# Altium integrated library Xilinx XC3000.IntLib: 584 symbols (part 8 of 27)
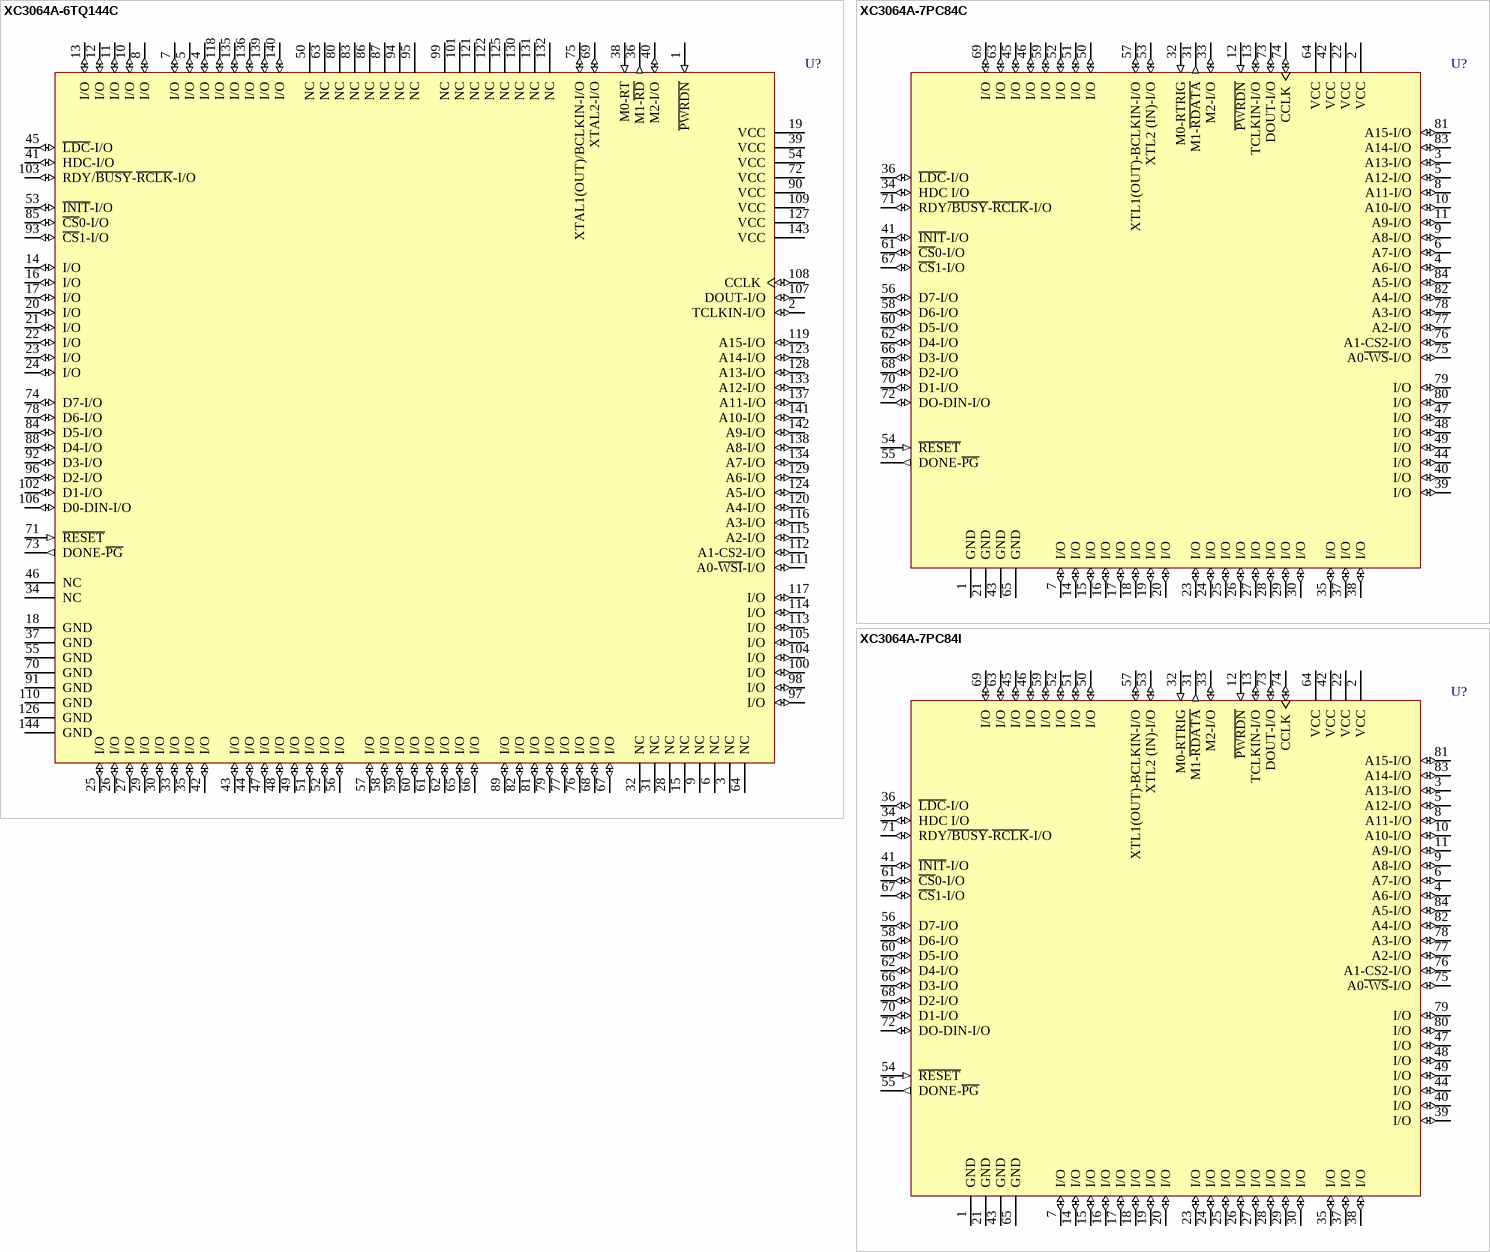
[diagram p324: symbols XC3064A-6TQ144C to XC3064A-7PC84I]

## XC3064A-7PC84I
designator U?
Logic Cell Array with 224 CLBs, with 70 I/O Pins, 84-Pin PLCC, Industrial Grade; ComponentAvailability: Not for New Design
footprint PC84_N (Leaded Chip Carrier, 84-Leads, Body 29.3x29.3mm, Pitch 1.27mm, IPC Medium Density)
footprint PC84_L (Leaded Chip Carrier, 84-Leads, Body 29.3x29.3mm, Pitch 1.27mm, IPC High Density)
footprint PC84_M (Leaded Chip Carrier, 84-Leads, Body 29.3x29.3mm, Pitch 1.27mm, IPC Low Density)
3D model XC3064A-PC84 (84-Pin Plastic Leaded Chip Carrier (PC84))
pins: 1 GND (power), 2 VCC (power), 3 A13-I/O (io), 4 A6-I/O (io), 5 A12-I/O (io), 6 A7-I/O (io), 7 I/O (io), 8 A11-I/O (io), 9 A8-I/O (io), 10 A10-I/O (io), 11 A9-I/O (io), 12 ~{PWRDN} (in), 13 TCLKIN-I/O (io), 14 I/O (io), 15 I/O (io), 16 I/O (io), 17 I/O (io), 18 I/O (io), 19 I/O (io), 20 I/O (io), 21 GND (power), 22 VCC (power), 23 I/O (io), 24 I/O (io), 25 I/O (io), 26 I/O (io), 27 I/O (io), 28 I/O (io), 29 I/O (io), 30 I/O (io), 31 M1-~{RDATA} (out), 32 M0-RTRIG (in), 33 M2-I/O (io), 34 HDC I/O (io), 35 I/O (io), 36 ~{LDC}-I/O (io), 37 I/O (io), 38 I/O (io), 39 I/O (io), 40 I/O (io), 41 ~{INIT}-I/O (io), 42 VCC (power), 43 GND (power), 44 I/O (io), 45 I/O (io), 46 I/O (io), 47 I/O (io), 48 I/O (io), 49 I/O (io), 50 I/O (io), 51 I/O (io), 52 I/O (io), 53 XTL2 (IN)-I/O (io), 54 ~{RESET} (in), 55 DONE-~{PG} (out), 56 D7-I/O (io), 57 XTL1(OUT)-BCLKIN-I/O (io), 58 D6-I/O (io), 59 I/O (io), 60 D5-I/O (io), 61 ~{CS}0-I/O (io), 62 D4-I/O (io), 63 I/O (io), 64 VCC (power), 65 GND (power), 66 D3-I/O (io), 67 ~{CS}1-I/O (io), 68 D2-I/O (io), 69 I/O (io), 70 D1-I/O (io), 71 RDY~{/BUSY}-~{RCLK}-I/O (io), 72 DO-DIN-I/O (io), 73 DOUT-I/O (io), 74 CCLK (io), 75 A0~{-WS}-I/O (io), 76 A1-CS2-I/O (io), 77 A2-I/O (io), 78 A3-I/O (io), 79 I/O (io), 80 I/O (io), 81 A15-I/O (io), 82 A4-I/O (io), 83 A14-I/O (io), 84 A5-I/O (io)

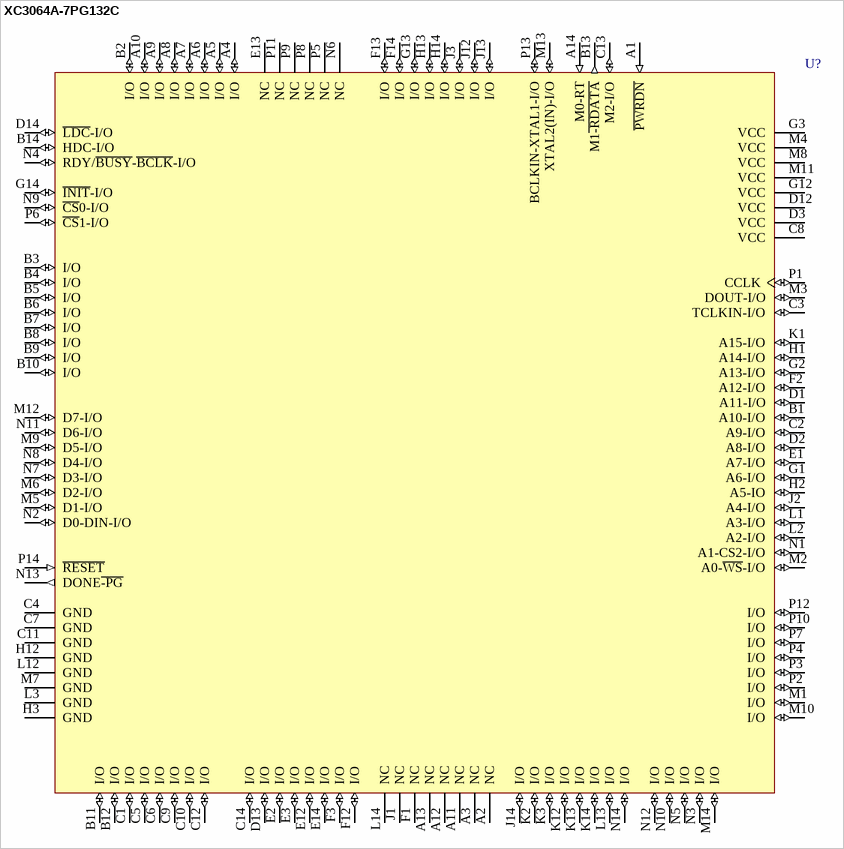
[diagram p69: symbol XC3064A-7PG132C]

## XC3064A-7PG132C
designator U?
Logic Cell Array with 224 CLBs, with 96 I/O Pins, 132-Pin PGA, Commercial Grade; ComponentAvailability: Not for New Design
footprint PG132 (PGA, 132-Leads, Body 37x37mm, Pitch 2.54mm)
3D model XC3064A-PG132 (132-Pin Ceramic Pin Grid Array (PG132))
pins: A1 ~{PWRDN} (in), A2 NC, A3 NC, A4 I/O (io), A5 I/O (io), A6 I/O (io), A7 I/O (io), A8 I/O (io), A9 I/O (io), A10 I/O (io), A11 NC, A12 NC, A13 NC, A14 M0-RT (in), B1 A10-I/O (io), B2 I/O (io), B3 I/O (io), B4 I/O (io), B5 I/O (io), B6 I/O (io), B7 I/O (io), B8 I/O (io), B9 I/O (io), B10 I/O (io), B11 I/O (io), B12 I/O (io), B13 M1~{-RDATA} (out), B14 HDC-I/O (io), C1 I/O (io), C2 A9-I/O (io), C3 TCLKIN-I/O (io), C4 GND (power), C5 I/O (io), C6 I/O (io), C7 GND (power), C8 VCC (power), C9 I/O (io), C10 I/O (io), C11 GND (power), C12 I/O (io), C13 M2-I/O (io), C14 I/O (io), D1 A11-I/O (io), D2 A8-I/O (io), D3 VCC (power), D12 VCC (power), D13 I/O (io), D14 ~{LDC}-I/O (io), E1 A7-I/O (io), E2 I/O (io), E3 I/O (io), E12 I/O (io), E13 NC, E14 I/O (io), F1 NC, F2 A12-I/O (io), F3 I/O (io), F12 I/O (io), F13 I/O (io), F14 I/O (io), G1 A6-I/O (io), G2 A13-I/O (io), G3 VCC (power), G12 VCC (power), G13 I/O (io), G14 ~{INIT}-I/O (io), H1 A14-I/O (io), H2 A5-IO (io), H3 GND (power), H12 GND (power), H13 I/O (io), H14 I/O (io), J1 NC, J2 A4-I/O (io), J3 I/O (io), J12 I/O (io), J13 I/O (io), J14 I/O (io), K1 A15-I/O (io), K2 I/O (io), K3 I/O (io), K12 I/O (io), K13 I/O (io), K14 I/O (io), L1 A3-I/O (io), L2 A2-I/O (io), L3 GND (power), L12 GND (power), L13 I/O (io), L14 NC, M1 I/O (io), M2 A0-~{WS}-I/O (io), M3 DOUT-I/O (io), M4 VCC (power), M5 D1-I/O (io), M6 D2-I/O (io), M7 GND (power), M8 VCC (power), M9 D5-I/O (io), M10 I/O (io), M11 VCC (power), M12 D7-I/O (io), M13 XTAL2(IN)-I/O (io), M14 I/O (io), N1 A1-CS2-I/O (io), N2 D0-DIN-I/O (io), N3 I/O (io), N4 RDY/~{BUSY}-~{BCLK}-I/O (io), N5 I/O (io), N6 NC, N7 D3-I/O (io), N8 D4-I/O (io), N9 ~{CS}0-I/O (io), N10 I/O (io), N11 D6-I/O (io), N12 I/O (io), N13 DONE~{-PG} (out), N14 I/O (io), P1 CCLK (io), P2 I/O (io), P3 I/O (io), P4 I/O (io), P5 NC, P6 ~{CS}1-I/O (io), P7 I/O (io), P8 NC, P9 NC, P10 I/O (io), P11 NC, P12 I/O (io), P13 BCLKIN-XTAL1-I/O (io), P14 ~{RESET} (in)

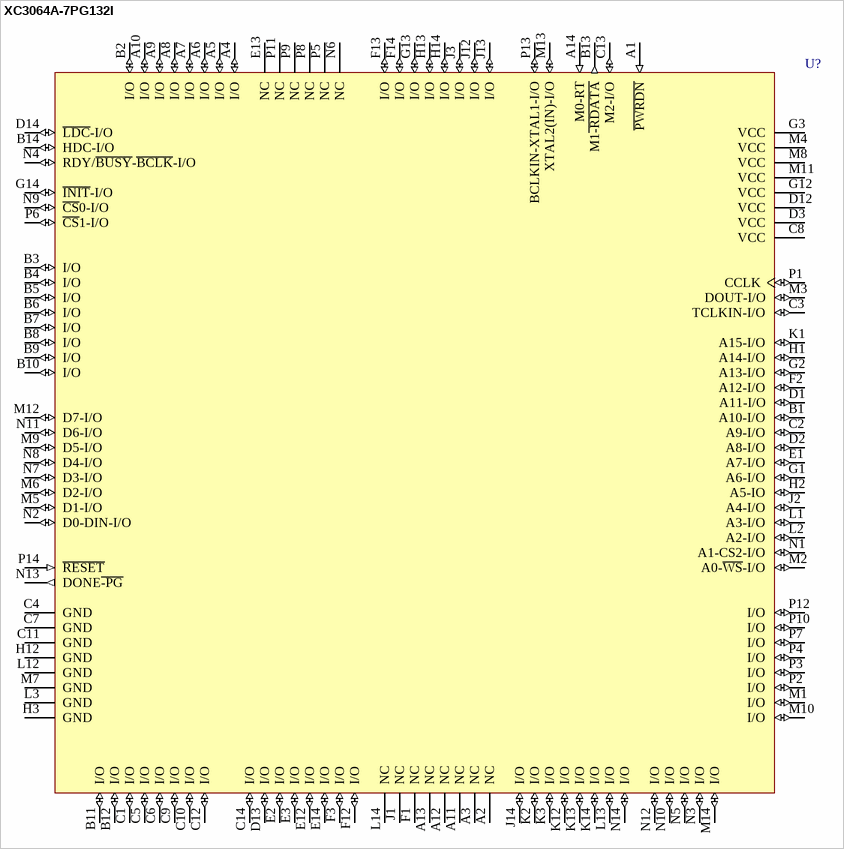
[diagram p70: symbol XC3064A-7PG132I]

## XC3064A-7PG132I
designator U?
Logic Cell Array with 224 CLBs, with 96 I/O Pins, 132-Pin PGA, Industrial Grade; ComponentAvailability: Not for New Design
footprint PG132 (PGA, 132-Leads, Body 37x37mm, Pitch 2.54mm)
3D model XC3064A-PG132 (132-Pin Ceramic Pin Grid Array (PG132))
pins: A1 ~{PWRDN} (in), A2 NC, A3 NC, A4 I/O (io), A5 I/O (io), A6 I/O (io), A7 I/O (io), A8 I/O (io), A9 I/O (io), A10 I/O (io), A11 NC, A12 NC, A13 NC, A14 M0-RT (in), B1 A10-I/O (io), B2 I/O (io), B3 I/O (io), B4 I/O (io), B5 I/O (io), B6 I/O (io), B7 I/O (io), B8 I/O (io), B9 I/O (io), B10 I/O (io), B11 I/O (io), B12 I/O (io), B13 M1~{-RDATA} (out), B14 HDC-I/O (io), C1 I/O (io), C2 A9-I/O (io), C3 TCLKIN-I/O (io), C4 GND (power), C5 I/O (io), C6 I/O (io), C7 GND (power), C8 VCC (power), C9 I/O (io), C10 I/O (io), C11 GND (power), C12 I/O (io), C13 M2-I/O (io), C14 I/O (io), D1 A11-I/O (io), D2 A8-I/O (io), D3 VCC (power), D12 VCC (power), D13 I/O (io), D14 ~{LDC}-I/O (io), E1 A7-I/O (io), E2 I/O (io), E3 I/O (io), E12 I/O (io), E13 NC, E14 I/O (io), F1 NC, F2 A12-I/O (io), F3 I/O (io), F12 I/O (io), F13 I/O (io), F14 I/O (io), G1 A6-I/O (io), G2 A13-I/O (io), G3 VCC (power), G12 VCC (power), G13 I/O (io), G14 ~{INIT}-I/O (io), H1 A14-I/O (io), H2 A5-IO (io), H3 GND (power), H12 GND (power), H13 I/O (io), H14 I/O (io), J1 NC, J2 A4-I/O (io), J3 I/O (io), J12 I/O (io), J13 I/O (io), J14 I/O (io), K1 A15-I/O (io), K2 I/O (io), K3 I/O (io), K12 I/O (io), K13 I/O (io), K14 I/O (io), L1 A3-I/O (io), L2 A2-I/O (io), L3 GND (power), L12 GND (power), L13 I/O (io), L14 NC, M1 I/O (io), M2 A0-~{WS}-I/O (io), M3 DOUT-I/O (io), M4 VCC (power), M5 D1-I/O (io), M6 D2-I/O (io), M7 GND (power), M8 VCC (power), M9 D5-I/O (io), M10 I/O (io), M11 VCC (power), M12 D7-I/O (io), M13 XTAL2(IN)-I/O (io), M14 I/O (io), N1 A1-CS2-I/O (io), N2 D0-DIN-I/O (io), N3 I/O (io), N4 RDY/~{BUSY}-~{BCLK}-I/O (io), N5 I/O (io), N6 NC, N7 D3-I/O (io), N8 D4-I/O (io), N9 ~{CS}0-I/O (io), N10 I/O (io), N11 D6-I/O (io), N12 I/O (io), N13 DONE~{-PG} (out), N14 I/O (io), P1 CCLK (io), P2 I/O (io), P3 I/O (io), P4 I/O (io), P5 NC, P6 ~{CS}1-I/O (io), P7 I/O (io), P8 NC, P9 NC, P10 I/O (io), P11 NC, P12 I/O (io), P13 BCLKIN-XTAL1-I/O (io), P14 ~{RESET} (in)

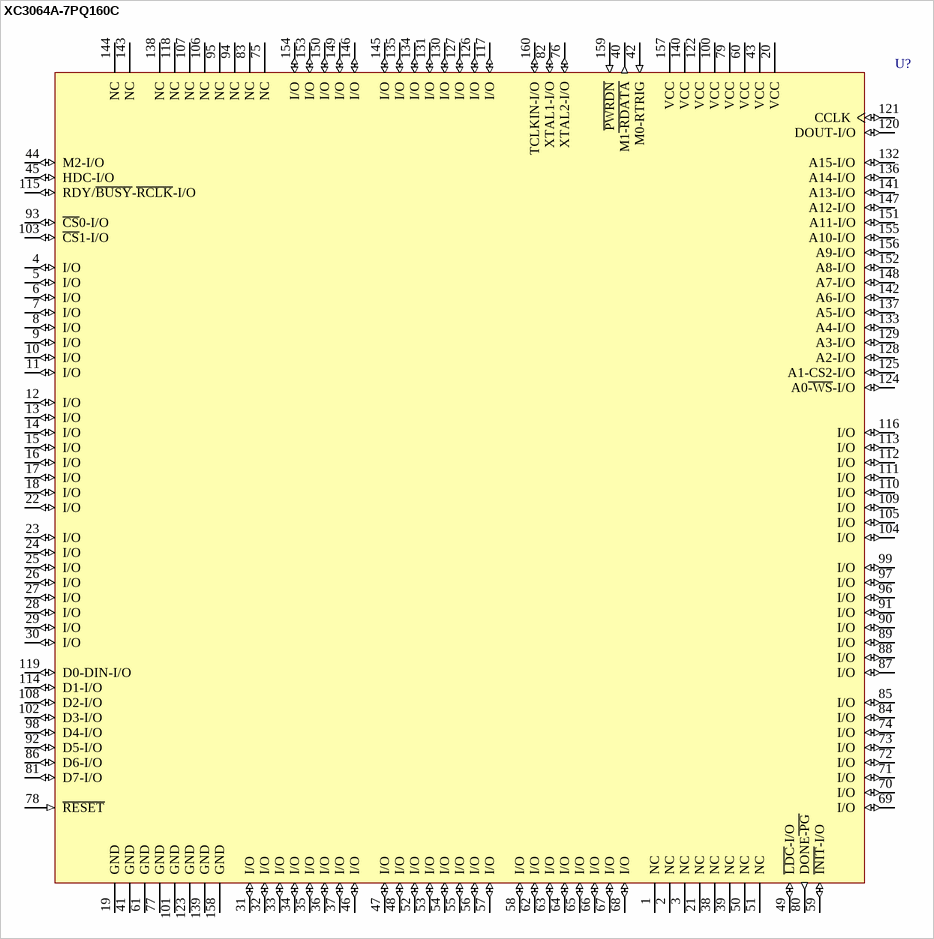
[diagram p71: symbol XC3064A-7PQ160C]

## XC3064A-7PQ160C
designator U?
Logic Cell Array with 224 CLBs, with 120 I/O Pins, 160-Pin PQFP, Commercial Grade; ComponentAvailability: Not for New Design
footprint PQ160_N (QFP, 160-Leads, Body 28 x 28mm, Pitch 0.65mm, IPC Medium Density)
footprint PQ160_L (QFP, 160-Leads, Body 28 x 28mm, Pitch 0.65mm, IPC High Density)
footprint PQ160_M (QFP, 160-Leads, Body 28 x 28mm, Pitch 0.65mm, IPC Low Density)
3D model XC3064A-PQ160 (160-Pin Plastic Quad Flat Pack (PQ160))
pins: 1 NC, 2 NC, 3 NC, 4 I/O (io), 5 I/O (io), 6 I/O (io), 7 I/O (io), 8 I/O (io), 9 I/O (io), 10 I/O (io), 11 I/O (io), 12 I/O (io), 13 I/O (io), 14 I/O (io), 15 I/O (io), 16 I/O (io), 17 I/O (io), 18 I/O (io), 19 GND (power), 20 VCC (power), 21 NC, 22 I/O (io), 23 I/O (io), 24 I/O (io), 25 I/O (io), 26 I/O (io), 27 I/O (io), 28 I/O (io), 29 I/O (io), 30 I/O (io), 31 I/O (io), 32 I/O (io), 33 I/O (io), 34 I/O (io), 35 I/O (io), 36 I/O (io), 37 I/O (io), 38 NC, 39 NC, 40 M1~{-RDATA} (out), 41 GND (power), 42 M0-RTRIG (in), 43 VCC (power), 44 M2-I/O (io), 45 HDC-I/O (io), 46 I/O (io), 47 I/O (io), 48 I/O (io), 49 ~{LDC}-I/O (io), 50 NC, 51 NC, 52 I/O (io), 53 I/O (io), 54 I/O (io), 55 I/O (io), 56 I/O (io), 57 I/O (io), 58 I/O (io), 59 ~{INIT}-I/O (io), 60 VCC (power), 61 GND (power), 62 I/O (io), 63 I/O (io), 64 I/O (io), 65 I/O (io), 66 I/O (io), 67 I/O (io), 68 I/O (io), 69 I/O (io), 70 I/O (io), 71 I/O (io), 72 I/O (io), 73 I/O (io), 74 I/O (io), 75 NC, 76 XTAL2-I/O (io), 77 GND (power), 78 ~{RESET} (in), 79 VCC (power), 80 DONE~{-PG} (out), 81 D7-I/O (io), 82 XTAL1-I/O (io), 83 NC, 84 I/O (io), 85 I/O (io), 86 D6-I/O (io), 87 I/O (io), 88 I/O (io), 89 I/O (io), 90 I/O (io), 91 I/O (io), 92 D5-I/O (io), 93 ~{CS}0-I/O (io), 94 NC, 95 NC, 96 I/O (io), 97 I/O (io), 98 D4-I/O (io), 99 I/O (io), 100 VCC (power), 101 GND (power), 102 D3-I/O (io), 103 ~{CS}1-I/O (io), 104 I/O (io), 105 I/O (io), 106 NC, 107 NC, 108 D2-I/O (io), 109 I/O (io), 110 I/O (io), 111 I/O (io), 112 I/O (io), 113 I/O (io), 114 D1-I/O (io), 115 RDY/~{BUSY}-~{RCLK}-I/O (io), 116 I/O (io), 117 I/O (io), 118 NC, 119 D0-DIN-I/O (io), 120 DOUT-I/O (io), 121 CCLK (io), 122 VCC (power), 123 GND (power), 124 A0~{-WS}-I/O (io), 125 A1-CS2-I/O (io), 126 I/O (io), 127 I/O (io), 128 A2-I/O (io), 129 A3-I/O (io), 130 I/O (io), 131 I/O (io), 132 A15-I/O (io), 133 A4-I/O (io), 134 I/O (io), 135 I/O (io), 136 A14-I/O (io), 137 A5-I/O (io), 138 NC, 139 GND (power), 140 VCC (power), 141 A13-I/O (io), 142 A6-I/O (io), 143 NC, 144 NC, 145 I/O (io), 146 I/O (io), 147 A12-I/O (io), 148 A7-I/O (io), 149 I/O (io), 150 I/O (io), 151 A11-I/O (io), 152 A8-I/O (io), 153 I/O (io), 154 I/O (io), 155 A10-I/O (io), 156 A9-I/O (io), 157 VCC (power), 158 GND (power), 159 ~{PWRDN} (in), 160 TCLKIN-I/O (io)

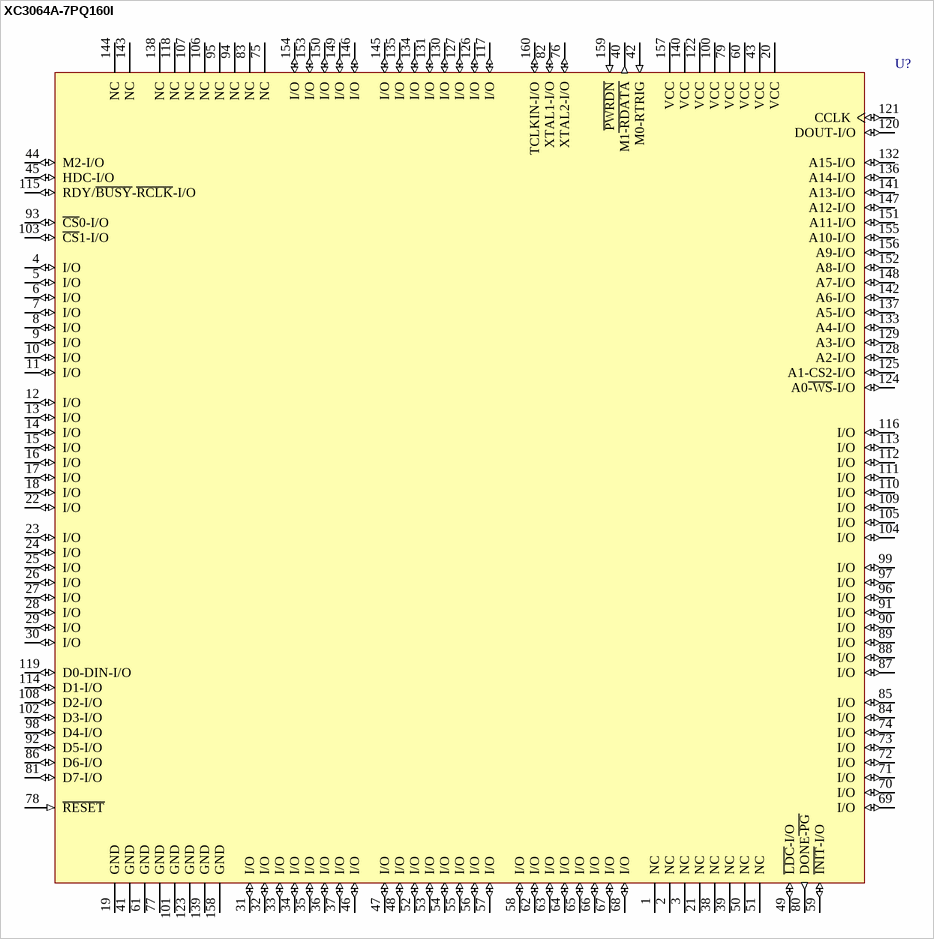
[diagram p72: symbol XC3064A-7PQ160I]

## XC3064A-7PQ160I
designator U?
Logic Cell Array with 224 CLBs, with 120 I/O Pins, 160-Pin PQFP, Industrial Grade; ComponentAvailability: Not for New Design
footprint PQ160_N (QFP, 160-Leads, Body 28 x 28mm, Pitch 0.65mm, IPC Medium Density)
footprint PQ160_L (QFP, 160-Leads, Body 28 x 28mm, Pitch 0.65mm, IPC High Density)
footprint PQ160_M (QFP, 160-Leads, Body 28 x 28mm, Pitch 0.65mm, IPC Low Density)
3D model XC3064A-PQ160 (160-Pin Plastic Quad Flat Pack (PQ160))
pins: 1 NC, 2 NC, 3 NC, 4 I/O (io), 5 I/O (io), 6 I/O (io), 7 I/O (io), 8 I/O (io), 9 I/O (io), 10 I/O (io), 11 I/O (io), 12 I/O (io), 13 I/O (io), 14 I/O (io), 15 I/O (io), 16 I/O (io), 17 I/O (io), 18 I/O (io), 19 GND (power), 20 VCC (power), 21 NC, 22 I/O (io), 23 I/O (io), 24 I/O (io), 25 I/O (io), 26 I/O (io), 27 I/O (io), 28 I/O (io), 29 I/O (io), 30 I/O (io), 31 I/O (io), 32 I/O (io), 33 I/O (io), 34 I/O (io), 35 I/O (io), 36 I/O (io), 37 I/O (io), 38 NC, 39 NC, 40 M1~{-RDATA} (out), 41 GND (power), 42 M0-RTRIG (in), 43 VCC (power), 44 M2-I/O (io), 45 HDC-I/O (io), 46 I/O (io), 47 I/O (io), 48 I/O (io), 49 ~{LDC}-I/O (io), 50 NC, 51 NC, 52 I/O (io), 53 I/O (io), 54 I/O (io), 55 I/O (io), 56 I/O (io), 57 I/O (io), 58 I/O (io), 59 ~{INIT}-I/O (io), 60 VCC (power), 61 GND (power), 62 I/O (io), 63 I/O (io), 64 I/O (io), 65 I/O (io), 66 I/O (io), 67 I/O (io), 68 I/O (io), 69 I/O (io), 70 I/O (io), 71 I/O (io), 72 I/O (io), 73 I/O (io), 74 I/O (io), 75 NC, 76 XTAL2-I/O (io), 77 GND (power), 78 ~{RESET} (in), 79 VCC (power), 80 DONE~{-PG} (out), 81 D7-I/O (io), 82 XTAL1-I/O (io), 83 NC, 84 I/O (io), 85 I/O (io), 86 D6-I/O (io), 87 I/O (io), 88 I/O (io), 89 I/O (io), 90 I/O (io), 91 I/O (io), 92 D5-I/O (io), 93 ~{CS}0-I/O (io), 94 NC, 95 NC, 96 I/O (io), 97 I/O (io), 98 D4-I/O (io), 99 I/O (io), 100 VCC (power), 101 GND (power), 102 D3-I/O (io), 103 ~{CS}1-I/O (io), 104 I/O (io), 105 I/O (io), 106 NC, 107 NC, 108 D2-I/O (io), 109 I/O (io), 110 I/O (io), 111 I/O (io), 112 I/O (io), 113 I/O (io), 114 D1-I/O (io), 115 RDY/~{BUSY}-~{RCLK}-I/O (io), 116 I/O (io), 117 I/O (io), 118 NC, 119 D0-DIN-I/O (io), 120 DOUT-I/O (io), 121 CCLK (io), 122 VCC (power), 123 GND (power), 124 A0~{-WS}-I/O (io), 125 A1-CS2-I/O (io), 126 I/O (io), 127 I/O (io), 128 A2-I/O (io), 129 A3-I/O (io), 130 I/O (io), 131 I/O (io), 132 A15-I/O (io), 133 A4-I/O (io), 134 I/O (io), 135 I/O (io), 136 A14-I/O (io), 137 A5-I/O (io), 138 NC, 139 GND (power), 140 VCC (power), 141 A13-I/O (io), 142 A6-I/O (io), 143 NC, 144 NC, 145 I/O (io), 146 I/O (io), 147 A12-I/O (io), 148 A7-I/O (io), 149 I/O (io), 150 I/O (io), 151 A11-I/O (io), 152 A8-I/O (io), 153 I/O (io), 154 I/O (io), 155 A10-I/O (io), 156 A9-I/O (io), 157 VCC (power), 158 GND (power), 159 ~{PWRDN} (in), 160 TCLKIN-I/O (io)

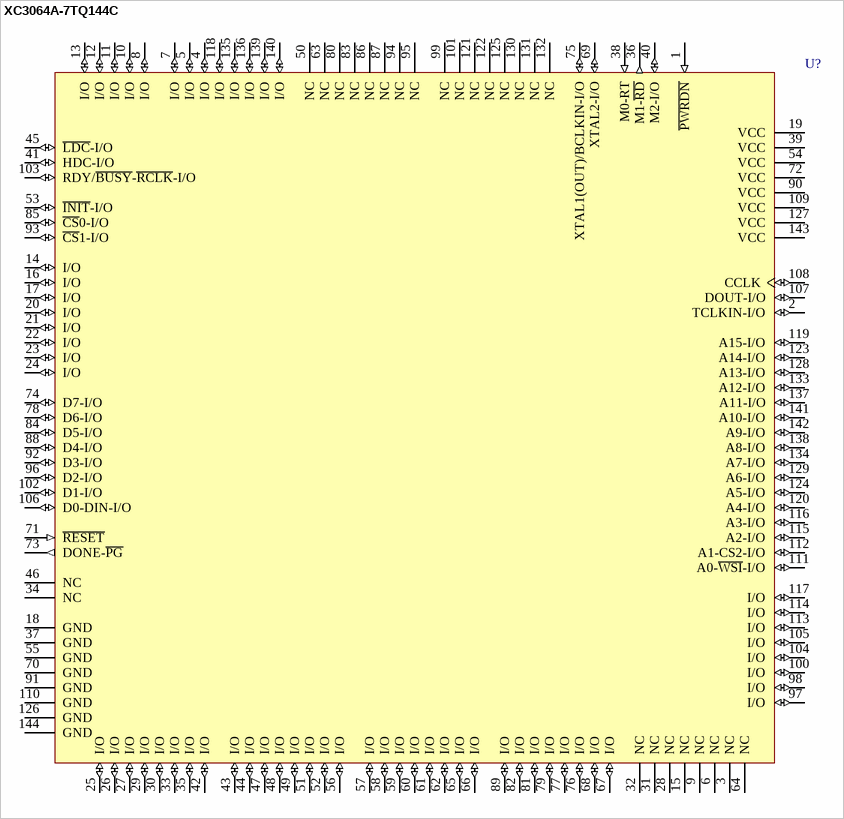
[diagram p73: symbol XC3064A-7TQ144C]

## XC3064A-7TQ144C
designator U?
Logic Cell Array with 224 CLBs, with 96 I/O Pins, 144-Pin TQFP, Commercial Grade; ComponentAvailability: Not for New Design
footprint TQ144_N (Thin QFP, 144-Leads, Body 20x20mm, Pitch 0.5mm, IPC Medium Density)
footprint TQ144_L (Thin QFP, 144-Leads, Body 20x20mm, Pitch 0.5mm, IPC High Density)
footprint TQ144_M (Thin QFP, 144-Leads, Body 20x20mm, Pitch 0.5mm, IPC Low Density)
3D model XC3064A-TQ144 (144-Pin Thin Quad Flat Pack (TQ144))
pins: 1 ~{PWRDN} (in), 2 TCLKIN-I/O (io), 3 NC, 4 I/O (io), 5 I/O (io), 6 NC, 7 I/O (io), 8 I/O (io), 9 NC, 10 I/O (io), 11 I/O (io), 12 I/O (io), 13 I/O (io), 14 I/O (io), 15 NC, 16 I/O (io), 17 I/O (io), 18 GND (power), 19 VCC (power), 20 I/O (io), 21 I/O (io), 22 I/O (io), 23 I/O (io), 24 I/O (io), 25 I/O (io), 26 I/O (io), 27 I/O (io), 28 NC, 29 I/O (io), 30 I/O (io), 31 NC, 32 NC, 33 I/O (io), 34 NC, 35 I/O (io), 36 M1-~{RD} (out), 37 GND (power), 38 M0-RT (in), 39 VCC (power), 40 M2-I/O (io), 41 HDC-I/O (io), 42 I/O (io), 43 I/O (io), 44 I/O (io), 45 ~{LDC}-I/O (io), 46 NC, 47 I/O (io), 48 I/O (io), 49 I/O (io), 50 NC, 51 I/O (io), 52 I/O (io), 53 ~{INIT}-I/O (io), 54 VCC (power), 55 GND (power), 56 I/O (io), 57 I/O (io), 58 I/O (io), 59 I/O (io), 60 I/O (io), 61 I/O (io), 62 I/O (io), 63 NC, 64 NC, 65 I/O (io), 66 I/O (io), 67 I/O (io), 68 I/O (io), 69 XTAL2-I/O (io), 70 GND (power), 71 ~{RESET} (in), 72 VCC (power), 73 DONE-~{PG} (out), 74 D7-I/O (io), 75 XTAL1(OUT)/BCLKIN-I/O (io), 76 I/O (io), 77 I/O (io), 78 D6-I/O (io), 79 I/O (io), 80 NC, 81 I/O (io), 82 I/O (io), 83 NC, 84 D5-I/O (io), 85 ~{CS}0-I/O (io), 86 NC, 87 NC, 88 D4-I/O (io), 89 I/O (io), 90 VCC (power), 91 GND (power), 92 D3-I/O (io), 93 ~{CS}1-I/O (io), 94 NC, 95 NC, 96 D2-I/O (io), 97 I/O (io), 98 I/O (io), 99 NC, 100 I/O (io), 101 NC, 102 D1-I/O (io), 103 RDY/~{BUSY}-~{RCLK}-I/O (io), 104 I/O (io), 105 I/O (io), 106 D0-DIN-I/O (io), 107 DOUT-I/O (io), 108 CCLK (io), 109 VCC (power), 110 GND (power), 111 A0-~{WSI}-I/O (io), 112 A1-CS2-I/O (io), 113 I/O (io), 114 I/O (io), 115 A2-I/O (io), 116 A3-I/O (io), 117 I/O (io), 118 I/O (io), 119 A15-I/O (io), 120 A4-I/O (io), 121 NC, 122 NC, 123 A14-I/O (io), 124 A5-I/O (io), 125 NC, 126 GND (power), 127 VCC (power), 128 A13-I/O (io), 129 A6-I/O (io), 130 NC, 131 NC, 132 NC, 133 A12-I/O (io), 134 A7-I/O (io), 135 I/O (io), 136 I/O (io), 137 A11-I/O (io), 138 A8-I/O (io), 139 I/O (io), 140 I/O (io), 141 A10-I/O (io), 142 A9-I/O (io), 143 VCC (power), 144 GND (power)

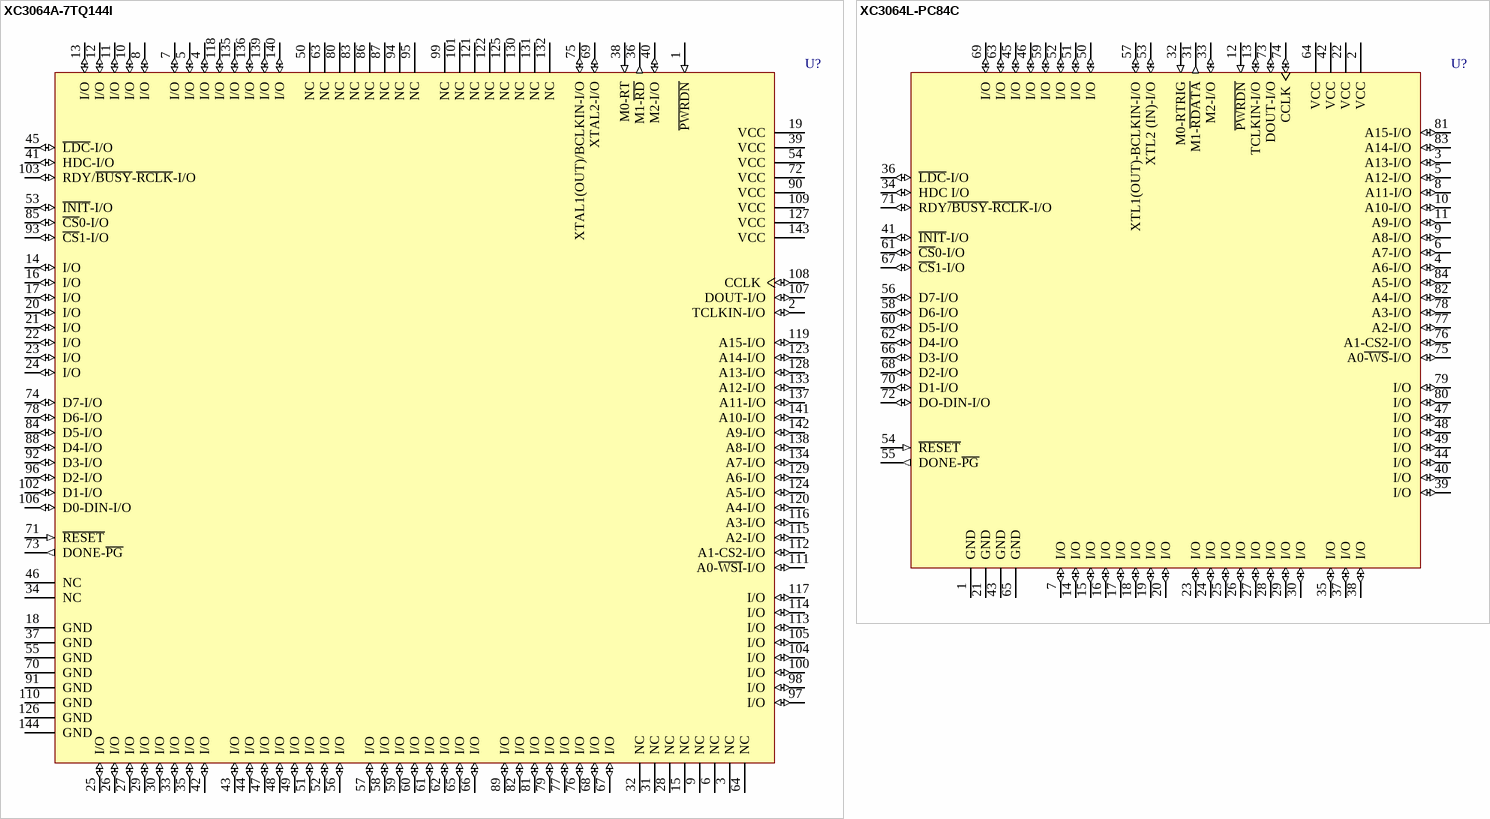
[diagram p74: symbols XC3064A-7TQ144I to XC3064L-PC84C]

## XC3064A-7TQ144I
designator U?
Logic Cell Array with 224 CLBs, with 96 I/O Pins, 144-Pin TQFP, Industrial Grade; ComponentAvailability: Not for New Design
footprint TQ144_N (Thin QFP, 144-Leads, Body 20x20mm, Pitch 0.5mm, IPC Medium Density)
footprint TQ144_L (Thin QFP, 144-Leads, Body 20x20mm, Pitch 0.5mm, IPC High Density)
footprint TQ144_M (Thin QFP, 144-Leads, Body 20x20mm, Pitch 0.5mm, IPC Low Density)
3D model XC3064A-TQ144 (144-Pin Thin Quad Flat Pack (TQ144))
pins: 1 ~{PWRDN} (in), 2 TCLKIN-I/O (io), 3 NC, 4 I/O (io), 5 I/O (io), 6 NC, 7 I/O (io), 8 I/O (io), 9 NC, 10 I/O (io), 11 I/O (io), 12 I/O (io), 13 I/O (io), 14 I/O (io), 15 NC, 16 I/O (io), 17 I/O (io), 18 GND (power), 19 VCC (power), 20 I/O (io), 21 I/O (io), 22 I/O (io), 23 I/O (io), 24 I/O (io), 25 I/O (io), 26 I/O (io), 27 I/O (io), 28 NC, 29 I/O (io), 30 I/O (io), 31 NC, 32 NC, 33 I/O (io), 34 NC, 35 I/O (io), 36 M1-~{RD} (out), 37 GND (power), 38 M0-RT (in), 39 VCC (power), 40 M2-I/O (io), 41 HDC-I/O (io), 42 I/O (io), 43 I/O (io), 44 I/O (io), 45 ~{LDC}-I/O (io), 46 NC, 47 I/O (io), 48 I/O (io), 49 I/O (io), 50 NC, 51 I/O (io), 52 I/O (io), 53 ~{INIT}-I/O (io), 54 VCC (power), 55 GND (power), 56 I/O (io), 57 I/O (io), 58 I/O (io), 59 I/O (io), 60 I/O (io), 61 I/O (io), 62 I/O (io), 63 NC, 64 NC, 65 I/O (io), 66 I/O (io), 67 I/O (io), 68 I/O (io), 69 XTAL2-I/O (io), 70 GND (power), 71 ~{RESET} (in), 72 VCC (power), 73 DONE-~{PG} (out), 74 D7-I/O (io), 75 XTAL1(OUT)/BCLKIN-I/O (io), 76 I/O (io), 77 I/O (io), 78 D6-I/O (io), 79 I/O (io), 80 NC, 81 I/O (io), 82 I/O (io), 83 NC, 84 D5-I/O (io), 85 ~{CS}0-I/O (io), 86 NC, 87 NC, 88 D4-I/O (io), 89 I/O (io), 90 VCC (power), 91 GND (power), 92 D3-I/O (io), 93 ~{CS}1-I/O (io), 94 NC, 95 NC, 96 D2-I/O (io), 97 I/O (io), 98 I/O (io), 99 NC, 100 I/O (io), 101 NC, 102 D1-I/O (io), 103 RDY/~{BUSY}-~{RCLK}-I/O (io), 104 I/O (io), 105 I/O (io), 106 D0-DIN-I/O (io), 107 DOUT-I/O (io), 108 CCLK (io), 109 VCC (power), 110 GND (power), 111 A0-~{WSI}-I/O (io), 112 A1-CS2-I/O (io), 113 I/O (io), 114 I/O (io), 115 A2-I/O (io), 116 A3-I/O (io), 117 I/O (io), 118 I/O (io), 119 A15-I/O (io), 120 A4-I/O (io), 121 NC, 122 NC, 123 A14-I/O (io), 124 A5-I/O (io), 125 NC, 126 GND (power), 127 VCC (power), 128 A13-I/O (io), 129 A6-I/O (io), 130 NC, 131 NC, 132 NC, 133 A12-I/O (io), 134 A7-I/O (io), 135 I/O (io), 136 I/O (io), 137 A11-I/O (io), 138 A8-I/O (io), 139 I/O (io), 140 I/O (io), 141 A10-I/O (io), 142 A9-I/O (io), 143 VCC (power), 144 GND (power)

## XC3064L-PC84C
designator U?
Logic Cell Array with 224 CLBs, with 70 I/O Pins, 84-Pin PLCC, Commercial Grade; ComponentAvailability: Not for New Design
footprint PC84_N (Leaded Chip Carrier, 84-Leads, Body 29.3x29.3mm, Pitch 1.27mm, IPC Medium Density)
footprint PC84_L (Leaded Chip Carrier, 84-Leads, Body 29.3x29.3mm, Pitch 1.27mm, IPC High Density)
footprint PC84_M (Leaded Chip Carrier, 84-Leads, Body 29.3x29.3mm, Pitch 1.27mm, IPC Low Density)
3D model XC3064L-PC84 (84-Pin Plastic Leaded Chip Carrier (PC84))
pins: 1 GND (power), 2 VCC (power), 3 A13-I/O (io), 4 A6-I/O (io), 5 A12-I/O (io), 6 A7-I/O (io), 7 I/O (io), 8 A11-I/O (io), 9 A8-I/O (io), 10 A10-I/O (io), 11 A9-I/O (io), 12 ~{PWRDN} (in), 13 TCLKIN-I/O (io), 14 I/O (io), 15 I/O (io), 16 I/O (io), 17 I/O (io), 18 I/O (io), 19 I/O (io), 20 I/O (io), 21 GND (power), 22 VCC (power), 23 I/O (io), 24 I/O (io), 25 I/O (io), 26 I/O (io), 27 I/O (io), 28 I/O (io), 29 I/O (io), 30 I/O (io), 31 M1-~{RDATA} (out), 32 M0-RTRIG (in), 33 M2-I/O (io), 34 HDC I/O (io), 35 I/O (io), 36 ~{LDC}-I/O (io), 37 I/O (io), 38 I/O (io), 39 I/O (io), 40 I/O (io), 41 ~{INIT}-I/O (io), 42 VCC (power), 43 GND (power), 44 I/O (io), 45 I/O (io), 46 I/O (io), 47 I/O (io), 48 I/O (io), 49 I/O (io), 50 I/O (io), 51 I/O (io), 52 I/O (io), 53 XTL2 (IN)-I/O (io), 54 ~{RESET} (in), 55 DONE-~{PG} (out), 56 D7-I/O (io), 57 XTL1(OUT)-BCLKIN-I/O (io), 58 D6-I/O (io), 59 I/O (io), 60 D5-I/O (io), 61 ~{CS}0-I/O (io), 62 D4-I/O (io), 63 I/O (io), 64 VCC (power), 65 GND (power), 66 D3-I/O (io), 67 ~{CS}1-I/O (io), 68 D2-I/O (io), 69 I/O (io), 70 D1-I/O (io), 71 RDY~{/BUSY}-~{RCLK}-I/O (io), 72 DO-DIN-I/O (io), 73 DOUT-I/O (io), 74 CCLK (io), 75 A0~{-WS}-I/O (io), 76 A1-CS2-I/O (io), 77 A2-I/O (io), 78 A3-I/O (io), 79 I/O (io), 80 I/O (io), 81 A15-I/O (io), 82 A4-I/O (io), 83 A14-I/O (io), 84 A5-I/O (io)

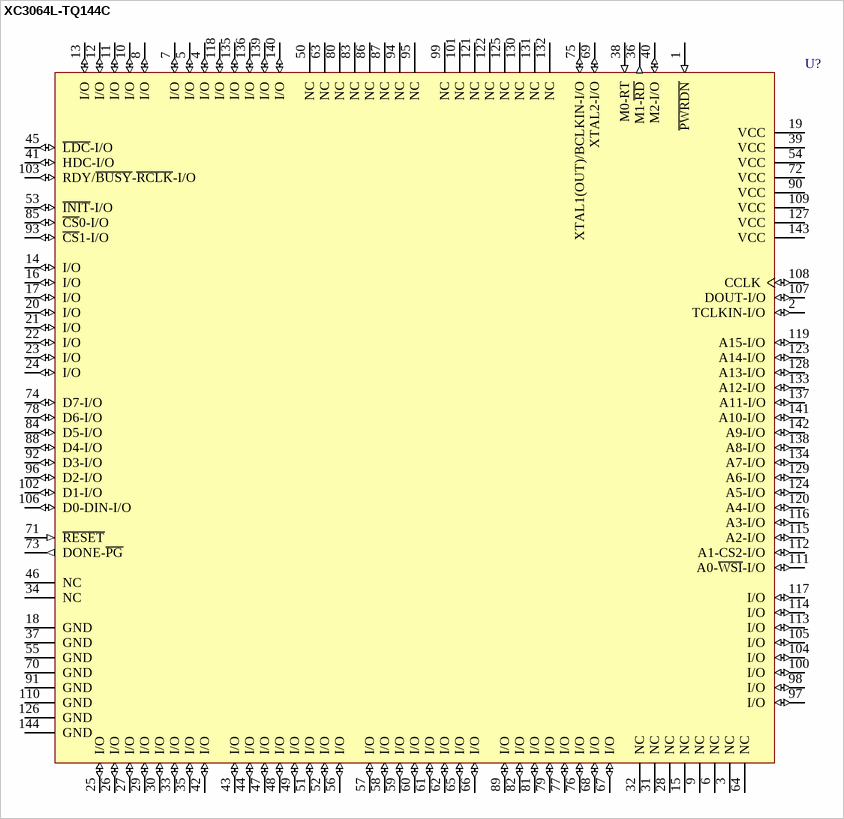
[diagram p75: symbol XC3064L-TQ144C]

## XC3064L-TQ144C
designator U?
Logic Cell Array with 224 CLBs, with 96 I/O Pins, 144-Pin TQFP, Commercial Grade; ComponentAvailability: Not for New Design
footprint TQ144_N (Thin QFP, 144-Leads, Body 20x20mm, Pitch 0.5mm, IPC Medium Density)
footprint TQ144_L (Thin QFP, 144-Leads, Body 20x20mm, Pitch 0.5mm, IPC High Density)
footprint TQ144_M (Thin QFP, 144-Leads, Body 20x20mm, Pitch 0.5mm, IPC Low Density)
3D model XC3064L-TQ144 (144-Pin Thin Quad Flat Pack (TQ144))
pins: 1 ~{PWRDN} (in), 2 TCLKIN-I/O (io), 3 NC, 4 I/O (io), 5 I/O (io), 6 NC, 7 I/O (io), 8 I/O (io), 9 NC, 10 I/O (io), 11 I/O (io), 12 I/O (io), 13 I/O (io), 14 I/O (io), 15 NC, 16 I/O (io), 17 I/O (io), 18 GND (power), 19 VCC (power), 20 I/O (io), 21 I/O (io), 22 I/O (io), 23 I/O (io), 24 I/O (io), 25 I/O (io), 26 I/O (io), 27 I/O (io), 28 NC, 29 I/O (io), 30 I/O (io), 31 NC, 32 NC, 33 I/O (io), 34 NC, 35 I/O (io), 36 M1-~{RD} (out), 37 GND (power), 38 M0-RT (in), 39 VCC (power), 40 M2-I/O (io), 41 HDC-I/O (io), 42 I/O (io), 43 I/O (io), 44 I/O (io), 45 ~{LDC}-I/O (io), 46 NC, 47 I/O (io), 48 I/O (io), 49 I/O (io), 50 NC, 51 I/O (io), 52 I/O (io), 53 ~{INIT}-I/O (io), 54 VCC (power), 55 GND (power), 56 I/O (io), 57 I/O (io), 58 I/O (io), 59 I/O (io), 60 I/O (io), 61 I/O (io), 62 I/O (io), 63 NC, 64 NC, 65 I/O (io), 66 I/O (io), 67 I/O (io), 68 I/O (io), 69 XTAL2-I/O (io), 70 GND (power), 71 ~{RESET} (in), 72 VCC (power), 73 DONE-~{PG} (out), 74 D7-I/O (io), 75 XTAL1(OUT)/BCLKIN-I/O (io), 76 I/O (io), 77 I/O (io), 78 D6-I/O (io), 79 I/O (io), 80 NC, 81 I/O (io), 82 I/O (io), 83 NC, 84 D5-I/O (io), 85 ~{CS}0-I/O (io), 86 NC, 87 NC, 88 D4-I/O (io), 89 I/O (io), 90 VCC (power), 91 GND (power), 92 D3-I/O (io), 93 ~{CS}1-I/O (io), 94 NC, 95 NC, 96 D2-I/O (io), 97 I/O (io), 98 I/O (io), 99 NC, 100 I/O (io), 101 NC, 102 D1-I/O (io), 103 RDY/~{BUSY}-~{RCLK}-I/O (io), 104 I/O (io), 105 I/O (io), 106 D0-DIN-I/O (io), 107 DOUT-I/O (io), 108 CCLK (io), 109 VCC (power), 110 GND (power), 111 A0-~{WSI}-I/O (io), 112 A1-CS2-I/O (io), 113 I/O (io), 114 I/O (io), 115 A2-I/O (io), 116 A3-I/O (io), 117 I/O (io), 118 I/O (io), 119 A15-I/O (io), 120 A4-I/O (io), 121 NC, 122 NC, 123 A14-I/O (io), 124 A5-I/O (io), 125 NC, 126 GND (power), 127 VCC (power), 128 A13-I/O (io), 129 A6-I/O (io), 130 NC, 131 NC, 132 NC, 133 A12-I/O (io), 134 A7-I/O (io), 135 I/O (io), 136 I/O (io), 137 A11-I/O (io), 138 A8-I/O (io), 139 I/O (io), 140 I/O (io), 141 A10-I/O (io), 142 A9-I/O (io), 143 VCC (power), 144 GND (power)

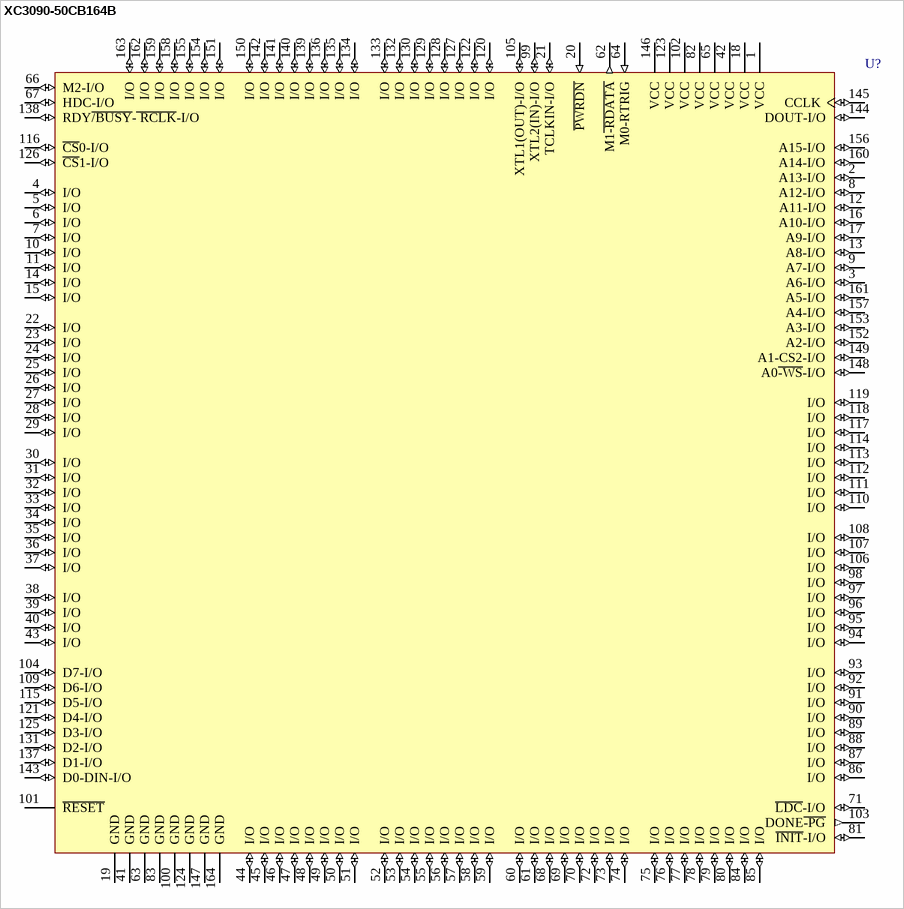
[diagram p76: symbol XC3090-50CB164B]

## XC3090-50CB164B
designator U?
Logic Cell Array with 320 CLBs, with 142 I/O Pins, 164-Pin CQFP, Military Class B Grade; ComponentAvailability: Not for New Design
footprint CB164_N (CQFP, 164-Leads, Body 29x29mm; Pitch 0.635mm, Gullwing Leadform, IPC Medium Density)
footprint CB164_L (CQFP, 164-Leads, Body 29x29mm; Pitch 0.635mm, Gullwing Leadform, IPC High Density)
footprint CB164_M (CQFP, 164-Leads, Body 29x29mm; Pitch 0.635mm, Gullwing Leadform, IPC Low Density)
3D model XC3090-CB164 (164-Pin Ceramic Brazed Quad Flat Pack (CB164))
pins: 1 VCC (power), 2 A13-I/O (io), 3 A6-I/O (io), 4 I/O (io), 5 I/O (io), 6 I/O (io), 7 I/O (io), 8 A12-I/O (io), 9 A7-I/O (io), 10 I/O (io), 11 I/O (io), 12 A11-I/O (io), 13 A8-I/O (io), 14 I/O (io), 15 I/O (io), 16 A10-I/O (io), 17 A9-I/O (io), 18 VCC (power), 19 GND (power), 20 ~{PWRDN} (in), 21 TCLKIN-I/O (io), 22 I/O (io), 23 I/O (io), 24 I/O (io), 25 I/O (io), 26 I/O (io), 27 I/O (io), 28 I/O (io), 29 I/O (io), 30 I/O (io), 31 I/O (io), 32 I/O (io), 33 I/O (io), 34 I/O (io), 35 I/O (io), 36 I/O (io), 37 I/O (io), 38 I/O (io), 39 I/O (io), 40 I/O (io), 41 GND (power), 42 VCC (power), 43 I/O (io), 44 I/O (io), 45 I/O (io), 46 I/O (io), 47 I/O (io), 48 I/O (io), 49 I/O (io), 50 I/O (io), 51 I/O (io), 52 I/O (io), 53 I/O (io), 54 I/O (io), 55 I/O (io), 56 I/O (io), 57 I/O (io), 58 I/O (io), 59 I/O (io), 60 I/O (io), 61 I/O (io), 62 M1~{-RDATA} (out), 63 GND (power), 64 M0-RTRIG (in), 65 VCC (power), 66 M2-I/O (io), 67 HDC-I/O (io), 68 I/O (io), 69 I/O (io), 70 I/O (io), 71 ~{LDC}-I/O (io), 72 I/O (io), 73 I/O (io), 74 I/O (io), 75 I/O (io), 76 I/O (io), 77 I/O (io), 78 I/O (io), 79 I/O (io), 80 I/O (io), 81 ~{INIT}-I/O (io), 82 VCC (power), 83 GND (power), 84 I/O (io), 85 I/O (io), 86 I/O (io), 87 I/O (io), 88 I/O (io), 89 I/O (io), 90 I/O (io), 91 I/O (io), 92 I/O (io), 93 I/O (io), 94 I/O (io), 95 I/O (io), 96 I/O (io), 97 I/O (io), 98 I/O (io), 99 XTL2(IN)-I/O (io), 100 GND (power), 101 ~{RESET} (oe), 102 VCC (power), 103 DONE~{-PG} (out), 104 D7-I/O (io), 105 XTL1(OUT)-I/O (io), 106 I/O (io), 107 I/O (io), 108 I/O (io), 109 D6-I/O (io), 110 I/O (io), 111 I/O (io), 112 I/O (io), 113 I/O (io), 114 I/O (io), 115 D5-I/O (io), 116 ~{CS}0-I/O (io), 117 I/O (io), 118 I/O (io), 119 I/O (io), 120 I/O (io), 121 D4-I/O (io), 122 I/O (io), 123 VCC (power), 124 GND (power), 125 D3-I/O (io), 126 ~{CS}1-I/O (io), 127 I/O (io), 128 I/O (io), 129 I/O (io), 130 I/O (io), 131 D2-I/O (io), 132 I/O (io), 133 I/O (io), 134 I/O (io), 135 I/O (io), 136 I/O (io), 137 D1-I/O (io), 138 RDY~{/BUSY}-~{ RCLK}-I/O (io), 139 I/O (io), 140 I/O (io), 141 I/O (io), 142 I/O (io), 143 D0-DIN-I/O (io), 144 DOUT-I/O (io), 145 CCLK (io), 146 VCC (power), 147 GND (power), 148 A0~{-WS}-I/O (io), 149 A1-CS2-I/O (io), 150 I/O (io), 151 I/O (io), 152 A2-I/O (io), 153 A3-I/O (io), 154 I/O (io), 155 I/O (io), 156 A15-I/O (io), 157 A4-I/O (io), 158 I/O (io), 159 I/O (io), 160 A14-I/O (io), 161 A5-I/O (io), 162 I/O (io), 163 I/O (io), 164 GND (power)

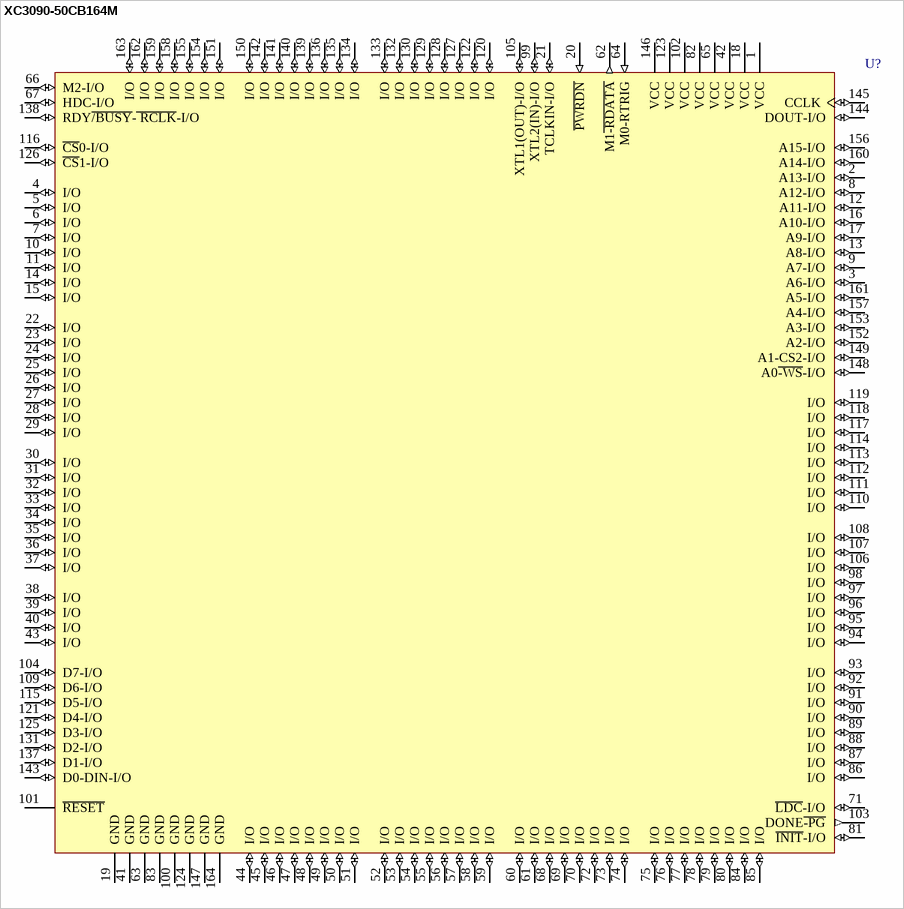
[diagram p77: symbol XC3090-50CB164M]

## XC3090-50CB164M
designator U?
Logic Cell Array with 320 CLBs, with 142 I/O Pins, 164-Pin CQFP, Military Grade; ComponentAvailability: Not for New Design
footprint CB164_N (CQFP, 164-Leads, Body 29x29mm; Pitch 0.635mm, Gullwing Leadform, IPC Medium Density)
footprint CB164_L (CQFP, 164-Leads, Body 29x29mm; Pitch 0.635mm, Gullwing Leadform, IPC High Density)
footprint CB164_M (CQFP, 164-Leads, Body 29x29mm; Pitch 0.635mm, Gullwing Leadform, IPC Low Density)
3D model XC3090-CB164 (164-Pin Ceramic Brazed Quad Flat Pack (CB164))
pins: 1 VCC (power), 2 A13-I/O (io), 3 A6-I/O (io), 4 I/O (io), 5 I/O (io), 6 I/O (io), 7 I/O (io), 8 A12-I/O (io), 9 A7-I/O (io), 10 I/O (io), 11 I/O (io), 12 A11-I/O (io), 13 A8-I/O (io), 14 I/O (io), 15 I/O (io), 16 A10-I/O (io), 17 A9-I/O (io), 18 VCC (power), 19 GND (power), 20 ~{PWRDN} (in), 21 TCLKIN-I/O (io), 22 I/O (io), 23 I/O (io), 24 I/O (io), 25 I/O (io), 26 I/O (io), 27 I/O (io), 28 I/O (io), 29 I/O (io), 30 I/O (io), 31 I/O (io), 32 I/O (io), 33 I/O (io), 34 I/O (io), 35 I/O (io), 36 I/O (io), 37 I/O (io), 38 I/O (io), 39 I/O (io), 40 I/O (io), 41 GND (power), 42 VCC (power), 43 I/O (io), 44 I/O (io), 45 I/O (io), 46 I/O (io), 47 I/O (io), 48 I/O (io), 49 I/O (io), 50 I/O (io), 51 I/O (io), 52 I/O (io), 53 I/O (io), 54 I/O (io), 55 I/O (io), 56 I/O (io), 57 I/O (io), 58 I/O (io), 59 I/O (io), 60 I/O (io), 61 I/O (io), 62 M1~{-RDATA} (out), 63 GND (power), 64 M0-RTRIG (in), 65 VCC (power), 66 M2-I/O (io), 67 HDC-I/O (io), 68 I/O (io), 69 I/O (io), 70 I/O (io), 71 ~{LDC}-I/O (io), 72 I/O (io), 73 I/O (io), 74 I/O (io), 75 I/O (io), 76 I/O (io), 77 I/O (io), 78 I/O (io), 79 I/O (io), 80 I/O (io), 81 ~{INIT}-I/O (io), 82 VCC (power), 83 GND (power), 84 I/O (io), 85 I/O (io), 86 I/O (io), 87 I/O (io), 88 I/O (io), 89 I/O (io), 90 I/O (io), 91 I/O (io), 92 I/O (io), 93 I/O (io), 94 I/O (io), 95 I/O (io), 96 I/O (io), 97 I/O (io), 98 I/O (io), 99 XTL2(IN)-I/O (io), 100 GND (power), 101 ~{RESET} (oe), 102 VCC (power), 103 DONE~{-PG} (out), 104 D7-I/O (io), 105 XTL1(OUT)-I/O (io), 106 I/O (io), 107 I/O (io), 108 I/O (io), 109 D6-I/O (io), 110 I/O (io), 111 I/O (io), 112 I/O (io), 113 I/O (io), 114 I/O (io), 115 D5-I/O (io), 116 ~{CS}0-I/O (io), 117 I/O (io), 118 I/O (io), 119 I/O (io), 120 I/O (io), 121 D4-I/O (io), 122 I/O (io), 123 VCC (power), 124 GND (power), 125 D3-I/O (io), 126 ~{CS}1-I/O (io), 127 I/O (io), 128 I/O (io), 129 I/O (io), 130 I/O (io), 131 D2-I/O (io), 132 I/O (io), 133 I/O (io), 134 I/O (io), 135 I/O (io), 136 I/O (io), 137 D1-I/O (io), 138 RDY~{/BUSY}-~{ RCLK}-I/O (io), 139 I/O (io), 140 I/O (io), 141 I/O (io), 142 I/O (io), 143 D0-DIN-I/O (io), 144 DOUT-I/O (io), 145 CCLK (io), 146 VCC (power), 147 GND (power), 148 A0~{-WS}-I/O (io), 149 A1-CS2-I/O (io), 150 I/O (io), 151 I/O (io), 152 A2-I/O (io), 153 A3-I/O (io), 154 I/O (io), 155 I/O (io), 156 A15-I/O (io), 157 A4-I/O (io), 158 I/O (io), 159 I/O (io), 160 A14-I/O (io), 161 A5-I/O (io), 162 I/O (io), 163 I/O (io), 164 GND (power)

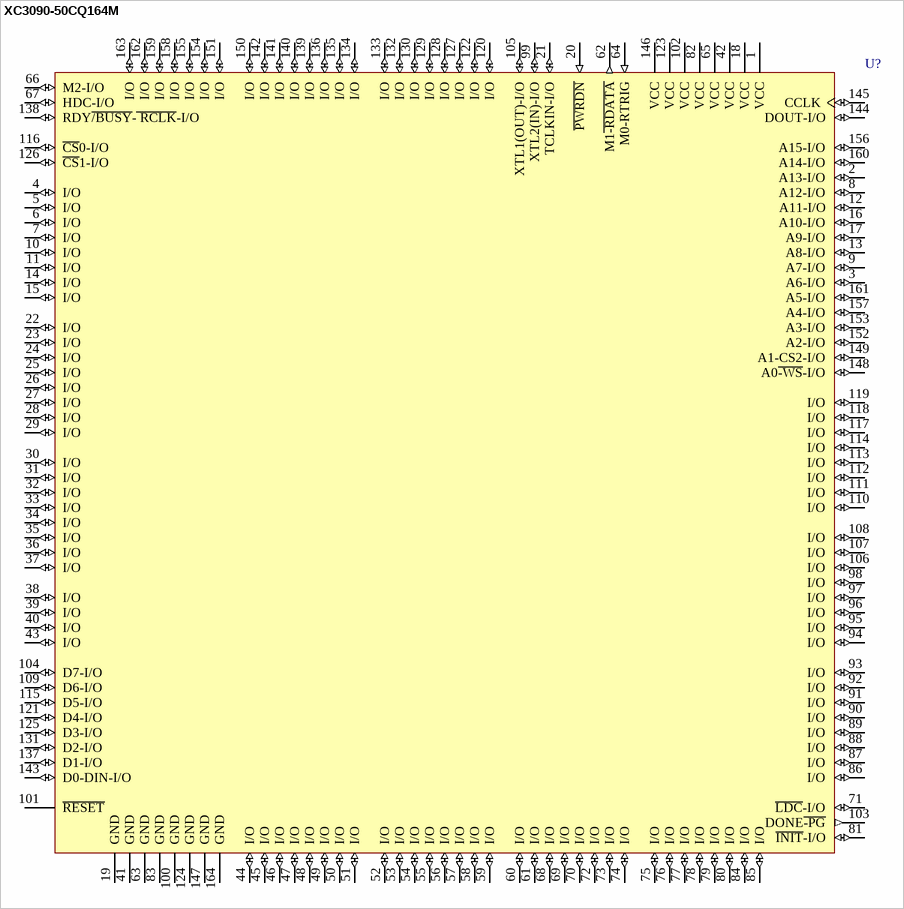
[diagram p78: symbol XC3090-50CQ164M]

## XC3090-50CQ164M
designator U?
Logic Cell Array with 320 CLBs, with 142 I/O Pins, 164-Pin CQFP, Military Grade; ComponentAvailability: Not for New Design
footprint CB164_N (CQFP, 164-Leads, Body 29x29mm; Pitch 0.635mm, Gullwing Leadform, IPC Medium Density)
footprint CB164_L (CQFP, 164-Leads, Body 29x29mm; Pitch 0.635mm, Gullwing Leadform, IPC High Density)
footprint CB164_M (CQFP, 164-Leads, Body 29x29mm; Pitch 0.635mm, Gullwing Leadform, IPC Low Density)
3D model XC3090-CB164 (164-Pin Ceramic Brazed Quad Flat Pack (CB164))
pins: 1 VCC (power), 2 A13-I/O (io), 3 A6-I/O (io), 4 I/O (io), 5 I/O (io), 6 I/O (io), 7 I/O (io), 8 A12-I/O (io), 9 A7-I/O (io), 10 I/O (io), 11 I/O (io), 12 A11-I/O (io), 13 A8-I/O (io), 14 I/O (io), 15 I/O (io), 16 A10-I/O (io), 17 A9-I/O (io), 18 VCC (power), 19 GND (power), 20 ~{PWRDN} (in), 21 TCLKIN-I/O (io), 22 I/O (io), 23 I/O (io), 24 I/O (io), 25 I/O (io), 26 I/O (io), 27 I/O (io), 28 I/O (io), 29 I/O (io), 30 I/O (io), 31 I/O (io), 32 I/O (io), 33 I/O (io), 34 I/O (io), 35 I/O (io), 36 I/O (io), 37 I/O (io), 38 I/O (io), 39 I/O (io), 40 I/O (io), 41 GND (power), 42 VCC (power), 43 I/O (io), 44 I/O (io), 45 I/O (io), 46 I/O (io), 47 I/O (io), 48 I/O (io), 49 I/O (io), 50 I/O (io), 51 I/O (io), 52 I/O (io), 53 I/O (io), 54 I/O (io), 55 I/O (io), 56 I/O (io), 57 I/O (io), 58 I/O (io), 59 I/O (io), 60 I/O (io), 61 I/O (io), 62 M1~{-RDATA} (out), 63 GND (power), 64 M0-RTRIG (in), 65 VCC (power), 66 M2-I/O (io), 67 HDC-I/O (io), 68 I/O (io), 69 I/O (io), 70 I/O (io), 71 ~{LDC}-I/O (io), 72 I/O (io), 73 I/O (io), 74 I/O (io), 75 I/O (io), 76 I/O (io), 77 I/O (io), 78 I/O (io), 79 I/O (io), 80 I/O (io), 81 ~{INIT}-I/O (io), 82 VCC (power), 83 GND (power), 84 I/O (io), 85 I/O (io), 86 I/O (io), 87 I/O (io), 88 I/O (io), 89 I/O (io), 90 I/O (io), 91 I/O (io), 92 I/O (io), 93 I/O (io), 94 I/O (io), 95 I/O (io), 96 I/O (io), 97 I/O (io), 98 I/O (io), 99 XTL2(IN)-I/O (io), 100 GND (power), 101 ~{RESET} (oe), 102 VCC (power), 103 DONE~{-PG} (out), 104 D7-I/O (io), 105 XTL1(OUT)-I/O (io), 106 I/O (io), 107 I/O (io), 108 I/O (io), 109 D6-I/O (io), 110 I/O (io), 111 I/O (io), 112 I/O (io), 113 I/O (io), 114 I/O (io), 115 D5-I/O (io), 116 ~{CS}0-I/O (io), 117 I/O (io), 118 I/O (io), 119 I/O (io), 120 I/O (io), 121 D4-I/O (io), 122 I/O (io), 123 VCC (power), 124 GND (power), 125 D3-I/O (io), 126 ~{CS}1-I/O (io), 127 I/O (io), 128 I/O (io), 129 I/O (io), 130 I/O (io), 131 D2-I/O (io), 132 I/O (io), 133 I/O (io), 134 I/O (io), 135 I/O (io), 136 I/O (io), 137 D1-I/O (io), 138 RDY~{/BUSY}-~{ RCLK}-I/O (io), 139 I/O (io), 140 I/O (io), 141 I/O (io), 142 I/O (io), 143 D0-DIN-I/O (io), 144 DOUT-I/O (io), 145 CCLK (io), 146 VCC (power), 147 GND (power), 148 A0~{-WS}-I/O (io), 149 A1-CS2-I/O (io), 150 I/O (io), 151 I/O (io), 152 A2-I/O (io), 153 A3-I/O (io), 154 I/O (io), 155 I/O (io), 156 A15-I/O (io), 157 A4-I/O (io), 158 I/O (io), 159 I/O (io), 160 A14-I/O (io), 161 A5-I/O (io), 162 I/O (io), 163 I/O (io), 164 GND (power)

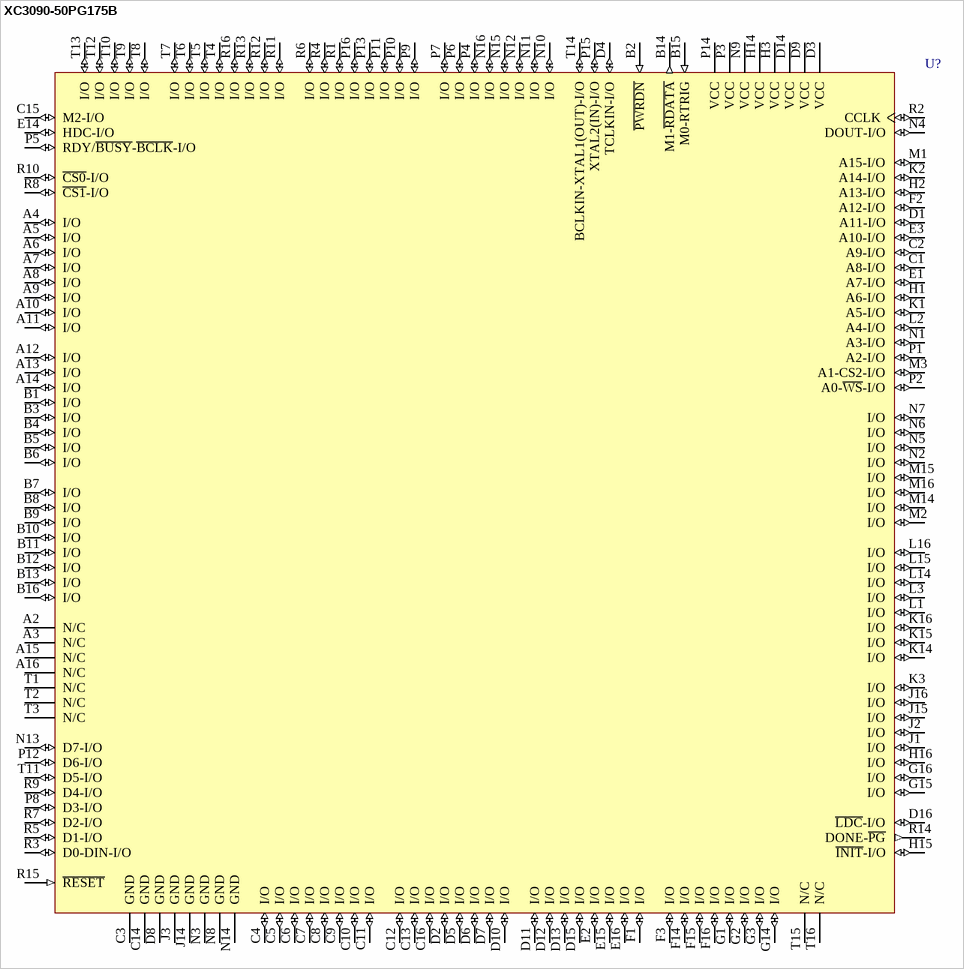
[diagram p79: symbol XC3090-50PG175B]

## XC3090-50PG175B
designator U?
Logic Cell Array with 320 CLBs, with 144 I/O Pins, 175-Pin PGA, Military Class B Grade; ComponentAvailability: Not for New Design
footprint PG175 (PGA, 175-Leads, Body 42x42mm, Pitch 2.54mm)
3D model XC3090-PG175 (175-Pin Ceramic Pin Grid Array (PG175))
pins: A2 N/C, A3 N/C, A4 I/O (io), A5 I/O (io), A6 I/O (io), A7 I/O (io), A8 I/O (io), A9 I/O (io), A10 I/O (io), A11 I/O (io), A12 I/O (io), A13 I/O (io), A14 I/O (io), A15 N/C, A16 N/C, B1 I/O (io), B2 ~{PWRDN} (in), B3 I/O (io), B4 I/O (io), B5 I/O (io), B6 I/O (io), B7 I/O (io), B8 I/O (io), B9 I/O (io), B10 I/O (io), B11 I/O (io), B12 I/O (io), B13 I/O (io), B14 M1-~{RDATA} (out), B15 M0-RTRIG (in), B16 I/O (io), C1 A8-I/O (io), C2 A9-I/O (io), C3 GND (power), C4 I/O (io), C5 I/O (io), C6 I/O (io), C7 I/O (io), C8 I/O (io), C9 I/O (io), C10 I/O (io), C11 I/O (io), C12 I/O (io), C13 I/O (io), C14 GND (power), C15 M2-I/O (io), C16 I/O (io), D1 A11-I/O (io), D2 I/O (io), D3 VCC (power), D4 TCLKIN-I/O (io), D5 I/O (io), D6 I/O (io), D7 I/O (io), D8 GND (power), D9 VCC (power), D10 I/O (io), D11 I/O (io), D12 I/O (io), D13 I/O (io), D14 VCC (power), D15 I/O (io), D16 ~{LDC}-I/O (io), E1 A7-I/O (io), E2 I/O (io), E3 A10-I/O (io), E14 HDC-I/O (io), E15 I/O (io), E16 I/O (io), F1 I/O (io), F2 A12-I/O (io), F3 I/O (io), F14 I/O (io), F15 I/O (io), F16 I/O (io), G1 I/O (io), G2 I/O (io), G3 I/O (io), G14 I/O (io), G15 I/O (io), G16 I/O (io), H1 A6-I/O (io), H2 A13-I/O (io), H3 VCC (power), H14 VCC (power), H15 ~{INIT}-I/O (io), H16 I/O (io), J1 I/O (io), J2 I/O (io), J3 GND (power), J14 GND (power), J15 I/O (io), J16 I/O (io), K1 A5-I/O (io), K2 A14-I/O (io), K3 I/O (io), K14 I/O (io), K15 I/O (io), K16 I/O (io), L1 I/O (io), L2 A4-I/O (io), L3 I/O (io), L14 I/O (io), L15 I/O (io), L16 I/O (io), M1 A15-I/O (io), M2 I/O (io), M3 A1-CS2-I/O (io), M14 I/O (io), M15 I/O (io), M16 I/O (io), N1 A3-I/O (io), N2 I/O (io), N3 GND (power), N4 DOUT-I/O (io), N5 I/O (io), N6 I/O (io), N7 I/O (io), N8 GND (power), N9 VCC (power), N10 I/O (io), N11 I/O (io), N12 I/O (io), N13 D7-I/O (io), N14 GND (power), N15 I/O (io), N16 I/O (io), P1 A2-I/O (io), P2 A0-~{WS}-I/O (io), P3 VCC (power), P4 I/O (io), P5 RDY/~{BUSY}-~{BCLK}-I/O (io), P6 I/O (io), P7 I/O (io), P8 D3-I/O (io), P9 I/O (io), P10 I/O (io), P11 I/O (io), P12 D6-I/O (io), P13 I/O (io), P14 VCC (power), P15 XTAL2(IN)-I/O (io), P16 I/O (io), R1 I/O (io), R2 CCLK (io), R3 D0-DIN-I/O (io), R4 I/O (io), R5 D1-I/O (io), R6 I/O (io), R7 D2-I/O (io), R8 ~{CS1}-I/O (io), R9 D4-I/O (io), R10 ~{CS0}-I/O (io), R11 I/O (io), R12 I/O (io), R13 I/O (io), R14 DONE-~{PG} (out), R15 ~{RESET} (in), R16 I/O (io), T1 N/C, T2 N/C, T3 N/C, T4 I/O (io), T5 I/O (io), T6 I/O (io), T7 I/O (io), T8 I/O (io), T9 I/O (io), T10 I/O (io), T11 D5-I/O (io), T12 I/O (io), T13 I/O (io), T14 BCLKIN-XTAL1(OUT)-I/O (io), T15 N/C, T16 N/C

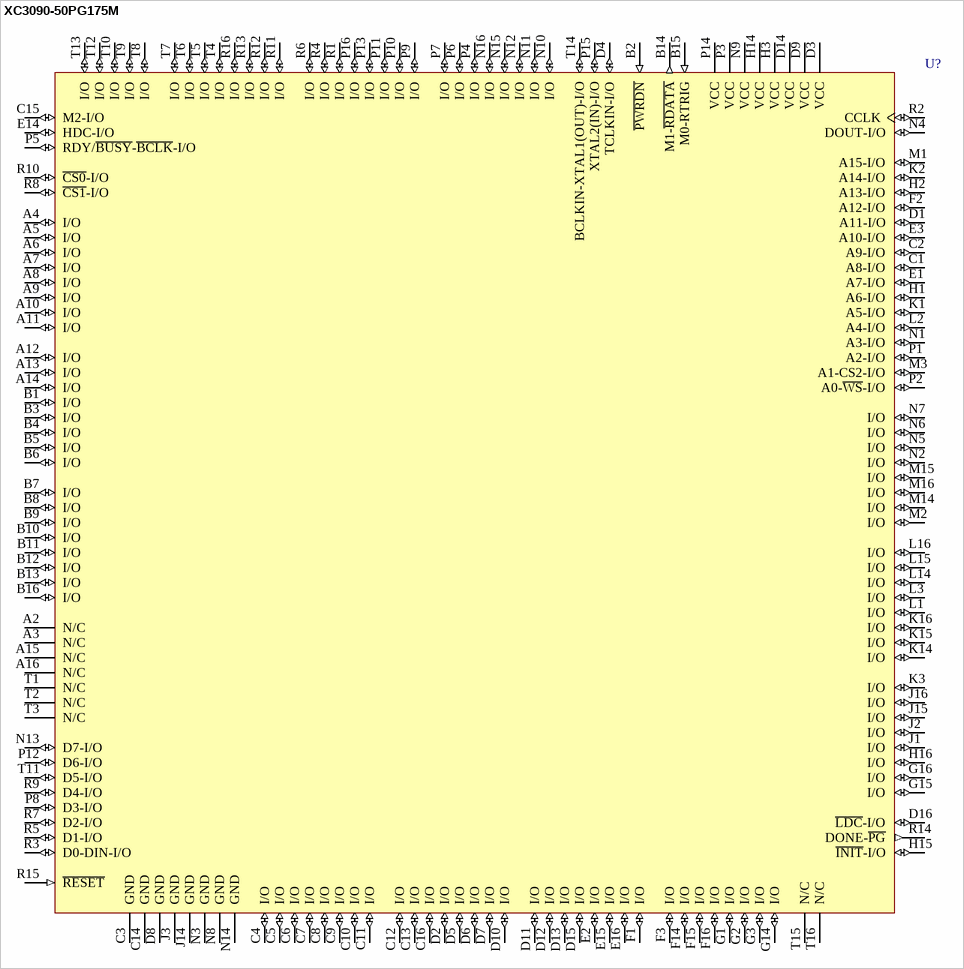
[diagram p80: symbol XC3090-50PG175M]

## XC3090-50PG175M
designator U?
Logic Cell Array with 320 CLBs, with 144 I/O Pins, 175-Pin PGA, Military Grade; ComponentAvailability: Not for New Design
footprint PG175 (PGA, 175-Leads, Body 42x42mm, Pitch 2.54mm)
3D model XC3090-PG175 (175-Pin Ceramic Pin Grid Array (PG175))
pins: A2 N/C, A3 N/C, A4 I/O (io), A5 I/O (io), A6 I/O (io), A7 I/O (io), A8 I/O (io), A9 I/O (io), A10 I/O (io), A11 I/O (io), A12 I/O (io), A13 I/O (io), A14 I/O (io), A15 N/C, A16 N/C, B1 I/O (io), B2 ~{PWRDN} (in), B3 I/O (io), B4 I/O (io), B5 I/O (io), B6 I/O (io), B7 I/O (io), B8 I/O (io), B9 I/O (io), B10 I/O (io), B11 I/O (io), B12 I/O (io), B13 I/O (io), B14 M1-~{RDATA} (out), B15 M0-RTRIG (in), B16 I/O (io), C1 A8-I/O (io), C2 A9-I/O (io), C3 GND (power), C4 I/O (io), C5 I/O (io), C6 I/O (io), C7 I/O (io), C8 I/O (io), C9 I/O (io), C10 I/O (io), C11 I/O (io), C12 I/O (io), C13 I/O (io), C14 GND (power), C15 M2-I/O (io), C16 I/O (io), D1 A11-I/O (io), D2 I/O (io), D3 VCC (power), D4 TCLKIN-I/O (io), D5 I/O (io), D6 I/O (io), D7 I/O (io), D8 GND (power), D9 VCC (power), D10 I/O (io), D11 I/O (io), D12 I/O (io), D13 I/O (io), D14 VCC (power), D15 I/O (io), D16 ~{LDC}-I/O (io), E1 A7-I/O (io), E2 I/O (io), E3 A10-I/O (io), E14 HDC-I/O (io), E15 I/O (io), E16 I/O (io), F1 I/O (io), F2 A12-I/O (io), F3 I/O (io), F14 I/O (io), F15 I/O (io), F16 I/O (io), G1 I/O (io), G2 I/O (io), G3 I/O (io), G14 I/O (io), G15 I/O (io), G16 I/O (io), H1 A6-I/O (io), H2 A13-I/O (io), H3 VCC (power), H14 VCC (power), H15 ~{INIT}-I/O (io), H16 I/O (io), J1 I/O (io), J2 I/O (io), J3 GND (power), J14 GND (power), J15 I/O (io), J16 I/O (io), K1 A5-I/O (io), K2 A14-I/O (io), K3 I/O (io), K14 I/O (io), K15 I/O (io), K16 I/O (io), L1 I/O (io), L2 A4-I/O (io), L3 I/O (io), L14 I/O (io), L15 I/O (io), L16 I/O (io), M1 A15-I/O (io), M2 I/O (io), M3 A1-CS2-I/O (io), M14 I/O (io), M15 I/O (io), M16 I/O (io), N1 A3-I/O (io), N2 I/O (io), N3 GND (power), N4 DOUT-I/O (io), N5 I/O (io), N6 I/O (io), N7 I/O (io), N8 GND (power), N9 VCC (power), N10 I/O (io), N11 I/O (io), N12 I/O (io), N13 D7-I/O (io), N14 GND (power), N15 I/O (io), N16 I/O (io), P1 A2-I/O (io), P2 A0-~{WS}-I/O (io), P3 VCC (power), P4 I/O (io), P5 RDY/~{BUSY}-~{BCLK}-I/O (io), P6 I/O (io), P7 I/O (io), P8 D3-I/O (io), P9 I/O (io), P10 I/O (io), P11 I/O (io), P12 D6-I/O (io), P13 I/O (io), P14 VCC (power), P15 XTAL2(IN)-I/O (io), P16 I/O (io), R1 I/O (io), R2 CCLK (io), R3 D0-DIN-I/O (io), R4 I/O (io), R5 D1-I/O (io), R6 I/O (io), R7 D2-I/O (io), R8 ~{CS1}-I/O (io), R9 D4-I/O (io), R10 ~{CS0}-I/O (io), R11 I/O (io), R12 I/O (io), R13 I/O (io), R14 DONE-~{PG} (out), R15 ~{RESET} (in), R16 I/O (io), T1 N/C, T2 N/C, T3 N/C, T4 I/O (io), T5 I/O (io), T6 I/O (io), T7 I/O (io), T8 I/O (io), T9 I/O (io), T10 I/O (io), T11 D5-I/O (io), T12 I/O (io), T13 I/O (io), T14 BCLKIN-XTAL1(OUT)-I/O (io), T15 N/C, T16 N/C

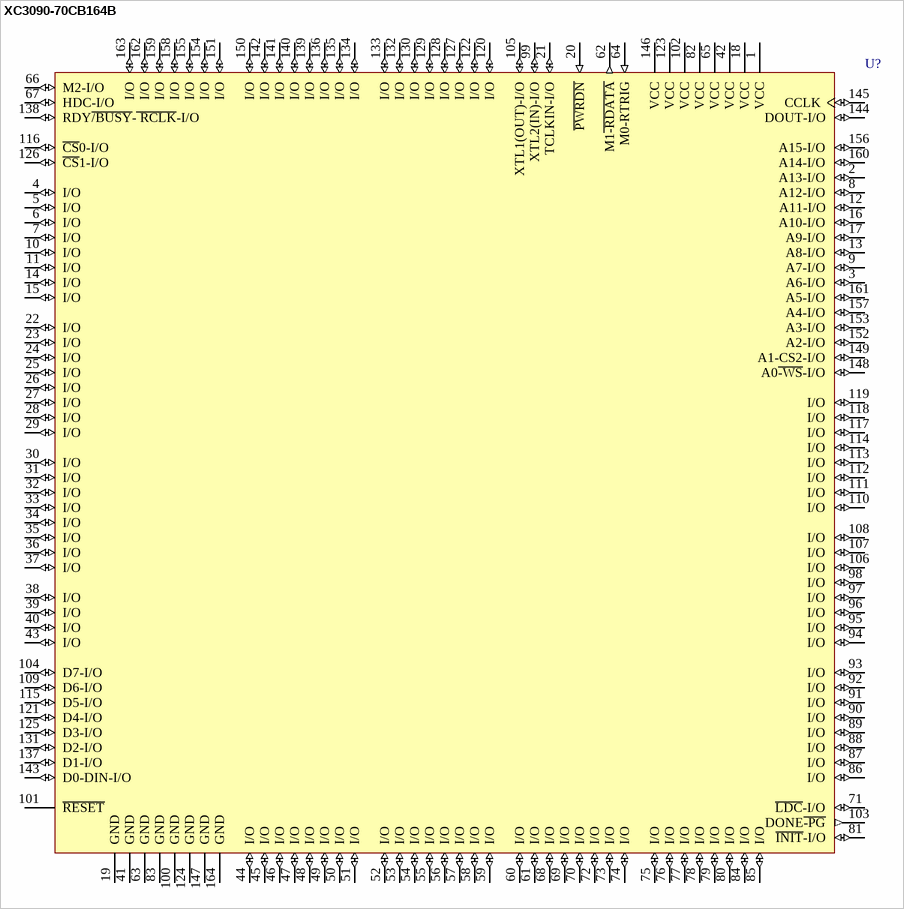
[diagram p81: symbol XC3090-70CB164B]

## XC3090-70CB164B
designator U?
Logic Cell Array with 320 CLBs, with 142 I/O Pins, 164-Pin CQFP, Military Class B Grade; ComponentAvailability: Not for New Design
footprint CB164_N (CQFP, 164-Leads, Body 29x29mm; Pitch 0.635mm, Gullwing Leadform, IPC Medium Density)
footprint CB164_L (CQFP, 164-Leads, Body 29x29mm; Pitch 0.635mm, Gullwing Leadform, IPC High Density)
footprint CB164_M (CQFP, 164-Leads, Body 29x29mm; Pitch 0.635mm, Gullwing Leadform, IPC Low Density)
3D model XC3090-CB164 (164-Pin Ceramic Brazed Quad Flat Pack (CB164))
pins: 1 VCC (power), 2 A13-I/O (io), 3 A6-I/O (io), 4 I/O (io), 5 I/O (io), 6 I/O (io), 7 I/O (io), 8 A12-I/O (io), 9 A7-I/O (io), 10 I/O (io), 11 I/O (io), 12 A11-I/O (io), 13 A8-I/O (io), 14 I/O (io), 15 I/O (io), 16 A10-I/O (io), 17 A9-I/O (io), 18 VCC (power), 19 GND (power), 20 ~{PWRDN} (in), 21 TCLKIN-I/O (io), 22 I/O (io), 23 I/O (io), 24 I/O (io), 25 I/O (io), 26 I/O (io), 27 I/O (io), 28 I/O (io), 29 I/O (io), 30 I/O (io), 31 I/O (io), 32 I/O (io), 33 I/O (io), 34 I/O (io), 35 I/O (io), 36 I/O (io), 37 I/O (io), 38 I/O (io), 39 I/O (io), 40 I/O (io), 41 GND (power), 42 VCC (power), 43 I/O (io), 44 I/O (io), 45 I/O (io), 46 I/O (io), 47 I/O (io), 48 I/O (io), 49 I/O (io), 50 I/O (io), 51 I/O (io), 52 I/O (io), 53 I/O (io), 54 I/O (io), 55 I/O (io), 56 I/O (io), 57 I/O (io), 58 I/O (io), 59 I/O (io), 60 I/O (io), 61 I/O (io), 62 M1~{-RDATA} (out), 63 GND (power), 64 M0-RTRIG (in), 65 VCC (power), 66 M2-I/O (io), 67 HDC-I/O (io), 68 I/O (io), 69 I/O (io), 70 I/O (io), 71 ~{LDC}-I/O (io), 72 I/O (io), 73 I/O (io), 74 I/O (io), 75 I/O (io), 76 I/O (io), 77 I/O (io), 78 I/O (io), 79 I/O (io), 80 I/O (io), 81 ~{INIT}-I/O (io), 82 VCC (power), 83 GND (power), 84 I/O (io), 85 I/O (io), 86 I/O (io), 87 I/O (io), 88 I/O (io), 89 I/O (io), 90 I/O (io), 91 I/O (io), 92 I/O (io), 93 I/O (io), 94 I/O (io), 95 I/O (io), 96 I/O (io), 97 I/O (io), 98 I/O (io), 99 XTL2(IN)-I/O (io), 100 GND (power), 101 ~{RESET} (oe), 102 VCC (power), 103 DONE~{-PG} (out), 104 D7-I/O (io), 105 XTL1(OUT)-I/O (io), 106 I/O (io), 107 I/O (io), 108 I/O (io), 109 D6-I/O (io), 110 I/O (io), 111 I/O (io), 112 I/O (io), 113 I/O (io), 114 I/O (io), 115 D5-I/O (io), 116 ~{CS}0-I/O (io), 117 I/O (io), 118 I/O (io), 119 I/O (io), 120 I/O (io), 121 D4-I/O (io), 122 I/O (io), 123 VCC (power), 124 GND (power), 125 D3-I/O (io), 126 ~{CS}1-I/O (io), 127 I/O (io), 128 I/O (io), 129 I/O (io), 130 I/O (io), 131 D2-I/O (io), 132 I/O (io), 133 I/O (io), 134 I/O (io), 135 I/O (io), 136 I/O (io), 137 D1-I/O (io), 138 RDY~{/BUSY}-~{ RCLK}-I/O (io), 139 I/O (io), 140 I/O (io), 141 I/O (io), 142 I/O (io), 143 D0-DIN-I/O (io), 144 DOUT-I/O (io), 145 CCLK (io), 146 VCC (power), 147 GND (power), 148 A0~{-WS}-I/O (io), 149 A1-CS2-I/O (io), 150 I/O (io), 151 I/O (io), 152 A2-I/O (io), 153 A3-I/O (io), 154 I/O (io), 155 I/O (io), 156 A15-I/O (io), 157 A4-I/O (io), 158 I/O (io), 159 I/O (io), 160 A14-I/O (io), 161 A5-I/O (io), 162 I/O (io), 163 I/O (io), 164 GND (power)

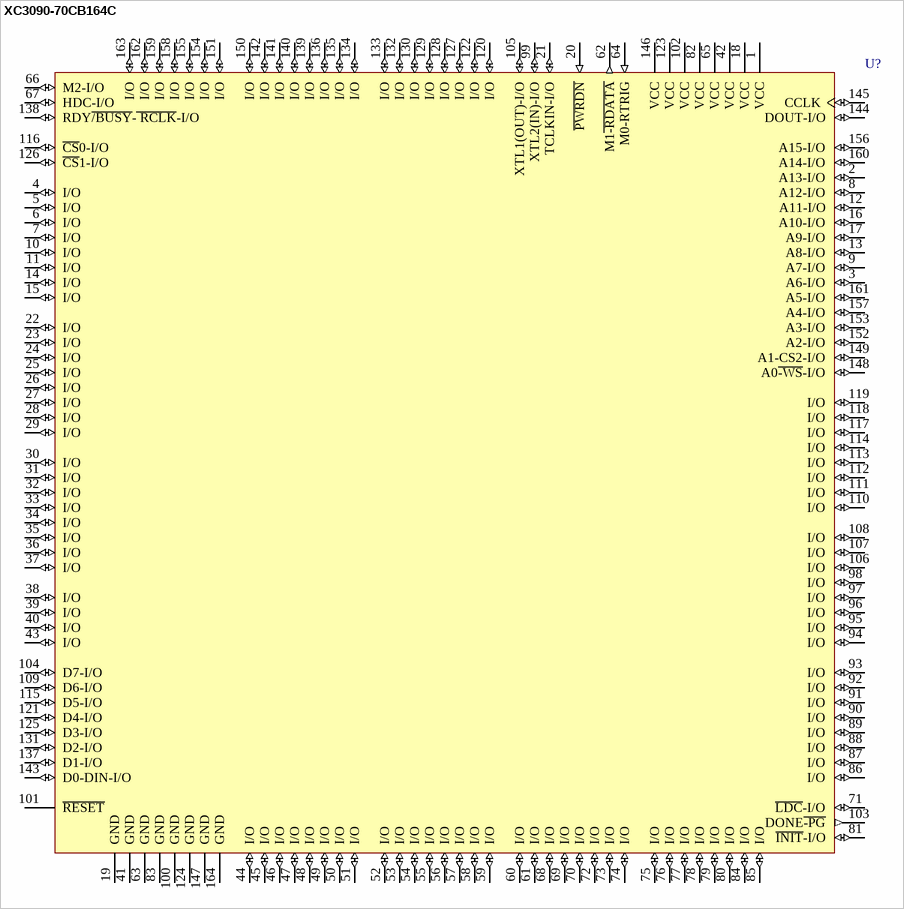
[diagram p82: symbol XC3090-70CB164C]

## XC3090-70CB164C
designator U?
Logic Cell Array with 320 CLBs, with 142 I/O Pins, 164-Pin CQFP, Commercial Grade; ComponentAvailability: Not for New Design
footprint CB164_N (CQFP, 164-Leads, Body 29x29mm; Pitch 0.635mm, Gullwing Leadform, IPC Medium Density)
footprint CB164_L (CQFP, 164-Leads, Body 29x29mm; Pitch 0.635mm, Gullwing Leadform, IPC High Density)
footprint CB164_M (CQFP, 164-Leads, Body 29x29mm; Pitch 0.635mm, Gullwing Leadform, IPC Low Density)
3D model XC3090-CB164 (164-Pin Ceramic Brazed Quad Flat Pack (CB164))
pins: 1 VCC (power), 2 A13-I/O (io), 3 A6-I/O (io), 4 I/O (io), 5 I/O (io), 6 I/O (io), 7 I/O (io), 8 A12-I/O (io), 9 A7-I/O (io), 10 I/O (io), 11 I/O (io), 12 A11-I/O (io), 13 A8-I/O (io), 14 I/O (io), 15 I/O (io), 16 A10-I/O (io), 17 A9-I/O (io), 18 VCC (power), 19 GND (power), 20 ~{PWRDN} (in), 21 TCLKIN-I/O (io), 22 I/O (io), 23 I/O (io), 24 I/O (io), 25 I/O (io), 26 I/O (io), 27 I/O (io), 28 I/O (io), 29 I/O (io), 30 I/O (io), 31 I/O (io), 32 I/O (io), 33 I/O (io), 34 I/O (io), 35 I/O (io), 36 I/O (io), 37 I/O (io), 38 I/O (io), 39 I/O (io), 40 I/O (io), 41 GND (power), 42 VCC (power), 43 I/O (io), 44 I/O (io), 45 I/O (io), 46 I/O (io), 47 I/O (io), 48 I/O (io), 49 I/O (io), 50 I/O (io), 51 I/O (io), 52 I/O (io), 53 I/O (io), 54 I/O (io), 55 I/O (io), 56 I/O (io), 57 I/O (io), 58 I/O (io), 59 I/O (io), 60 I/O (io), 61 I/O (io), 62 M1~{-RDATA} (out), 63 GND (power), 64 M0-RTRIG (in), 65 VCC (power), 66 M2-I/O (io), 67 HDC-I/O (io), 68 I/O (io), 69 I/O (io), 70 I/O (io), 71 ~{LDC}-I/O (io), 72 I/O (io), 73 I/O (io), 74 I/O (io), 75 I/O (io), 76 I/O (io), 77 I/O (io), 78 I/O (io), 79 I/O (io), 80 I/O (io), 81 ~{INIT}-I/O (io), 82 VCC (power), 83 GND (power), 84 I/O (io), 85 I/O (io), 86 I/O (io), 87 I/O (io), 88 I/O (io), 89 I/O (io), 90 I/O (io), 91 I/O (io), 92 I/O (io), 93 I/O (io), 94 I/O (io), 95 I/O (io), 96 I/O (io), 97 I/O (io), 98 I/O (io), 99 XTL2(IN)-I/O (io), 100 GND (power), 101 ~{RESET} (oe), 102 VCC (power), 103 DONE~{-PG} (out), 104 D7-I/O (io), 105 XTL1(OUT)-I/O (io), 106 I/O (io), 107 I/O (io), 108 I/O (io), 109 D6-I/O (io), 110 I/O (io), 111 I/O (io), 112 I/O (io), 113 I/O (io), 114 I/O (io), 115 D5-I/O (io), 116 ~{CS}0-I/O (io), 117 I/O (io), 118 I/O (io), 119 I/O (io), 120 I/O (io), 121 D4-I/O (io), 122 I/O (io), 123 VCC (power), 124 GND (power), 125 D3-I/O (io), 126 ~{CS}1-I/O (io), 127 I/O (io), 128 I/O (io), 129 I/O (io), 130 I/O (io), 131 D2-I/O (io), 132 I/O (io), 133 I/O (io), 134 I/O (io), 135 I/O (io), 136 I/O (io), 137 D1-I/O (io), 138 RDY~{/BUSY}-~{ RCLK}-I/O (io), 139 I/O (io), 140 I/O (io), 141 I/O (io), 142 I/O (io), 143 D0-DIN-I/O (io), 144 DOUT-I/O (io), 145 CCLK (io), 146 VCC (power), 147 GND (power), 148 A0~{-WS}-I/O (io), 149 A1-CS2-I/O (io), 150 I/O (io), 151 I/O (io), 152 A2-I/O (io), 153 A3-I/O (io), 154 I/O (io), 155 I/O (io), 156 A15-I/O (io), 157 A4-I/O (io), 158 I/O (io), 159 I/O (io), 160 A14-I/O (io), 161 A5-I/O (io), 162 I/O (io), 163 I/O (io), 164 GND (power)

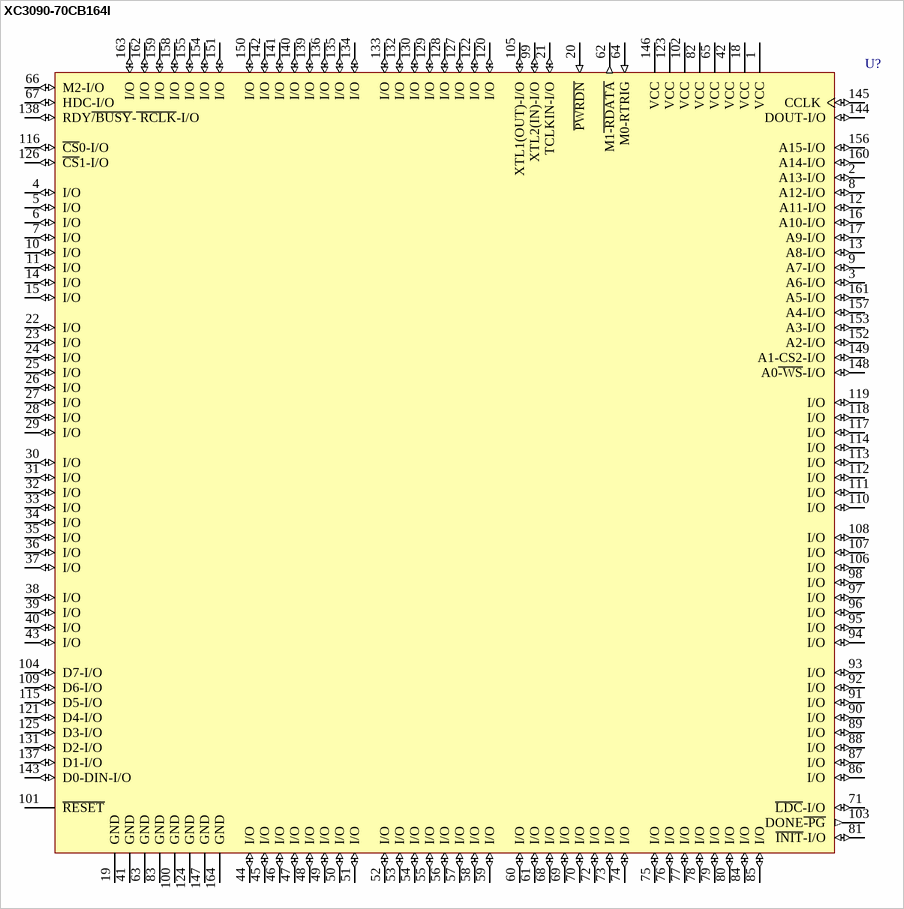
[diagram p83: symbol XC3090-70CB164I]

## XC3090-70CB164I
designator U?
Logic Cell Array with 320 CLBs, with 142 I/O Pins, 164-Pin CQFP, Industrial Grade; ComponentAvailability: Not for New Design
footprint CB164_N (CQFP, 164-Leads, Body 29x29mm; Pitch 0.635mm, Gullwing Leadform, IPC Medium Density)
footprint CB164_L (CQFP, 164-Leads, Body 29x29mm; Pitch 0.635mm, Gullwing Leadform, IPC High Density)
footprint CB164_M (CQFP, 164-Leads, Body 29x29mm; Pitch 0.635mm, Gullwing Leadform, IPC Low Density)
3D model XC3090-CB164 (164-Pin Ceramic Brazed Quad Flat Pack (CB164))
pins: 1 VCC (power), 2 A13-I/O (io), 3 A6-I/O (io), 4 I/O (io), 5 I/O (io), 6 I/O (io), 7 I/O (io), 8 A12-I/O (io), 9 A7-I/O (io), 10 I/O (io), 11 I/O (io), 12 A11-I/O (io), 13 A8-I/O (io), 14 I/O (io), 15 I/O (io), 16 A10-I/O (io), 17 A9-I/O (io), 18 VCC (power), 19 GND (power), 20 ~{PWRDN} (in), 21 TCLKIN-I/O (io), 22 I/O (io), 23 I/O (io), 24 I/O (io), 25 I/O (io), 26 I/O (io), 27 I/O (io), 28 I/O (io), 29 I/O (io), 30 I/O (io), 31 I/O (io), 32 I/O (io), 33 I/O (io), 34 I/O (io), 35 I/O (io), 36 I/O (io), 37 I/O (io), 38 I/O (io), 39 I/O (io), 40 I/O (io), 41 GND (power), 42 VCC (power), 43 I/O (io), 44 I/O (io), 45 I/O (io), 46 I/O (io), 47 I/O (io), 48 I/O (io), 49 I/O (io), 50 I/O (io), 51 I/O (io), 52 I/O (io), 53 I/O (io), 54 I/O (io), 55 I/O (io), 56 I/O (io), 57 I/O (io), 58 I/O (io), 59 I/O (io), 60 I/O (io), 61 I/O (io), 62 M1~{-RDATA} (out), 63 GND (power), 64 M0-RTRIG (in), 65 VCC (power), 66 M2-I/O (io), 67 HDC-I/O (io), 68 I/O (io), 69 I/O (io), 70 I/O (io), 71 ~{LDC}-I/O (io), 72 I/O (io), 73 I/O (io), 74 I/O (io), 75 I/O (io), 76 I/O (io), 77 I/O (io), 78 I/O (io), 79 I/O (io), 80 I/O (io), 81 ~{INIT}-I/O (io), 82 VCC (power), 83 GND (power), 84 I/O (io), 85 I/O (io), 86 I/O (io), 87 I/O (io), 88 I/O (io), 89 I/O (io), 90 I/O (io), 91 I/O (io), 92 I/O (io), 93 I/O (io), 94 I/O (io), 95 I/O (io), 96 I/O (io), 97 I/O (io), 98 I/O (io), 99 XTL2(IN)-I/O (io), 100 GND (power), 101 ~{RESET} (oe), 102 VCC (power), 103 DONE~{-PG} (out), 104 D7-I/O (io), 105 XTL1(OUT)-I/O (io), 106 I/O (io), 107 I/O (io), 108 I/O (io), 109 D6-I/O (io), 110 I/O (io), 111 I/O (io), 112 I/O (io), 113 I/O (io), 114 I/O (io), 115 D5-I/O (io), 116 ~{CS}0-I/O (io), 117 I/O (io), 118 I/O (io), 119 I/O (io), 120 I/O (io), 121 D4-I/O (io), 122 I/O (io), 123 VCC (power), 124 GND (power), 125 D3-I/O (io), 126 ~{CS}1-I/O (io), 127 I/O (io), 128 I/O (io), 129 I/O (io), 130 I/O (io), 131 D2-I/O (io), 132 I/O (io), 133 I/O (io), 134 I/O (io), 135 I/O (io), 136 I/O (io), 137 D1-I/O (io), 138 RDY~{/BUSY}-~{ RCLK}-I/O (io), 139 I/O (io), 140 I/O (io), 141 I/O (io), 142 I/O (io), 143 D0-DIN-I/O (io), 144 DOUT-I/O (io), 145 CCLK (io), 146 VCC (power), 147 GND (power), 148 A0~{-WS}-I/O (io), 149 A1-CS2-I/O (io), 150 I/O (io), 151 I/O (io), 152 A2-I/O (io), 153 A3-I/O (io), 154 I/O (io), 155 I/O (io), 156 A15-I/O (io), 157 A4-I/O (io), 158 I/O (io), 159 I/O (io), 160 A14-I/O (io), 161 A5-I/O (io), 162 I/O (io), 163 I/O (io), 164 GND (power)

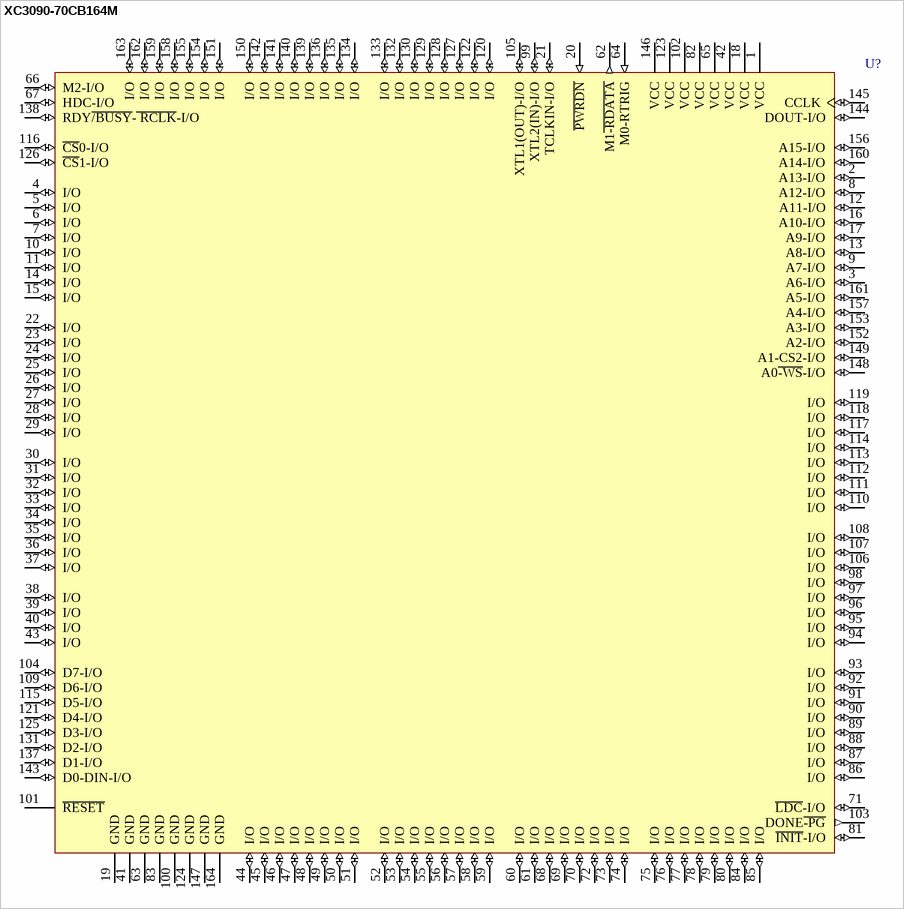
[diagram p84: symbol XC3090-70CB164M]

## XC3090-70CB164M
designator U?
Logic Cell Array with 320 CLBs, with 142 I/O Pins, 164-Pin CQFP, Military Grade; ComponentAvailability: Not for New Design
footprint CB164_N (CQFP, 164-Leads, Body 29x29mm; Pitch 0.635mm, Gullwing Leadform, IPC Medium Density)
footprint CB164_L (CQFP, 164-Leads, Body 29x29mm; Pitch 0.635mm, Gullwing Leadform, IPC High Density)
footprint CB164_M (CQFP, 164-Leads, Body 29x29mm; Pitch 0.635mm, Gullwing Leadform, IPC Low Density)
3D model XC3090-CB164 (164-Pin Ceramic Brazed Quad Flat Pack (CB164))
pins: 1 VCC (power), 2 A13-I/O (io), 3 A6-I/O (io), 4 I/O (io), 5 I/O (io), 6 I/O (io), 7 I/O (io), 8 A12-I/O (io), 9 A7-I/O (io), 10 I/O (io), 11 I/O (io), 12 A11-I/O (io), 13 A8-I/O (io), 14 I/O (io), 15 I/O (io), 16 A10-I/O (io), 17 A9-I/O (io), 18 VCC (power), 19 GND (power), 20 ~{PWRDN} (in), 21 TCLKIN-I/O (io), 22 I/O (io), 23 I/O (io), 24 I/O (io), 25 I/O (io), 26 I/O (io), 27 I/O (io), 28 I/O (io), 29 I/O (io), 30 I/O (io), 31 I/O (io), 32 I/O (io), 33 I/O (io), 34 I/O (io), 35 I/O (io), 36 I/O (io), 37 I/O (io), 38 I/O (io), 39 I/O (io), 40 I/O (io), 41 GND (power), 42 VCC (power), 43 I/O (io), 44 I/O (io), 45 I/O (io), 46 I/O (io), 47 I/O (io), 48 I/O (io), 49 I/O (io), 50 I/O (io), 51 I/O (io), 52 I/O (io), 53 I/O (io), 54 I/O (io), 55 I/O (io), 56 I/O (io), 57 I/O (io), 58 I/O (io), 59 I/O (io), 60 I/O (io), 61 I/O (io), 62 M1~{-RDATA} (out), 63 GND (power), 64 M0-RTRIG (in), 65 VCC (power), 66 M2-I/O (io), 67 HDC-I/O (io), 68 I/O (io), 69 I/O (io), 70 I/O (io), 71 ~{LDC}-I/O (io), 72 I/O (io), 73 I/O (io), 74 I/O (io), 75 I/O (io), 76 I/O (io), 77 I/O (io), 78 I/O (io), 79 I/O (io), 80 I/O (io), 81 ~{INIT}-I/O (io), 82 VCC (power), 83 GND (power), 84 I/O (io), 85 I/O (io), 86 I/O (io), 87 I/O (io), 88 I/O (io), 89 I/O (io), 90 I/O (io), 91 I/O (io), 92 I/O (io), 93 I/O (io), 94 I/O (io), 95 I/O (io), 96 I/O (io), 97 I/O (io), 98 I/O (io), 99 XTL2(IN)-I/O (io), 100 GND (power), 101 ~{RESET} (oe), 102 VCC (power), 103 DONE~{-PG} (out), 104 D7-I/O (io), 105 XTL1(OUT)-I/O (io), 106 I/O (io), 107 I/O (io), 108 I/O (io), 109 D6-I/O (io), 110 I/O (io), 111 I/O (io), 112 I/O (io), 113 I/O (io), 114 I/O (io), 115 D5-I/O (io), 116 ~{CS}0-I/O (io), 117 I/O (io), 118 I/O (io), 119 I/O (io), 120 I/O (io), 121 D4-I/O (io), 122 I/O (io), 123 VCC (power), 124 GND (power), 125 D3-I/O (io), 126 ~{CS}1-I/O (io), 127 I/O (io), 128 I/O (io), 129 I/O (io), 130 I/O (io), 131 D2-I/O (io), 132 I/O (io), 133 I/O (io), 134 I/O (io), 135 I/O (io), 136 I/O (io), 137 D1-I/O (io), 138 RDY~{/BUSY}-~{ RCLK}-I/O (io), 139 I/O (io), 140 I/O (io), 141 I/O (io), 142 I/O (io), 143 D0-DIN-I/O (io), 144 DOUT-I/O (io), 145 CCLK (io), 146 VCC (power), 147 GND (power), 148 A0~{-WS}-I/O (io), 149 A1-CS2-I/O (io), 150 I/O (io), 151 I/O (io), 152 A2-I/O (io), 153 A3-I/O (io), 154 I/O (io), 155 I/O (io), 156 A15-I/O (io), 157 A4-I/O (io), 158 I/O (io), 159 I/O (io), 160 A14-I/O (io), 161 A5-I/O (io), 162 I/O (io), 163 I/O (io), 164 GND (power)

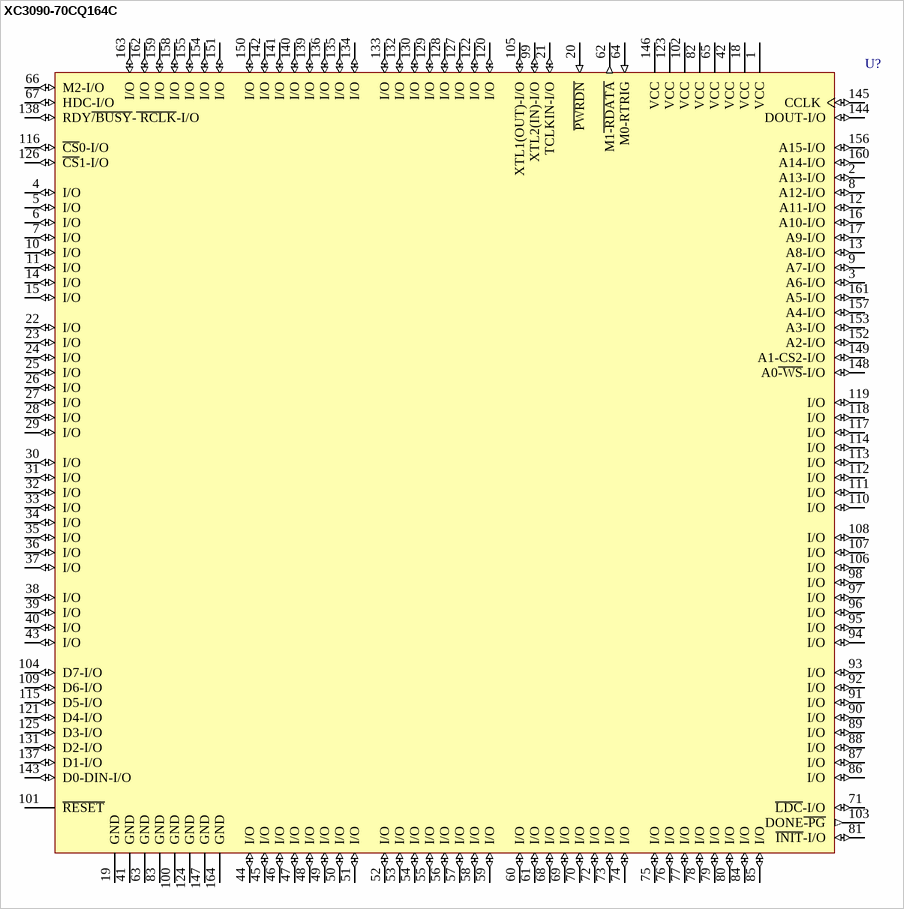
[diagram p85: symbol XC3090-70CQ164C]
